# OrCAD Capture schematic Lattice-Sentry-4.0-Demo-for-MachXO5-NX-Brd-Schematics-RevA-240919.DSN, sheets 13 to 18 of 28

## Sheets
13 Certus Pro NX Bank 7 (BMC): size B
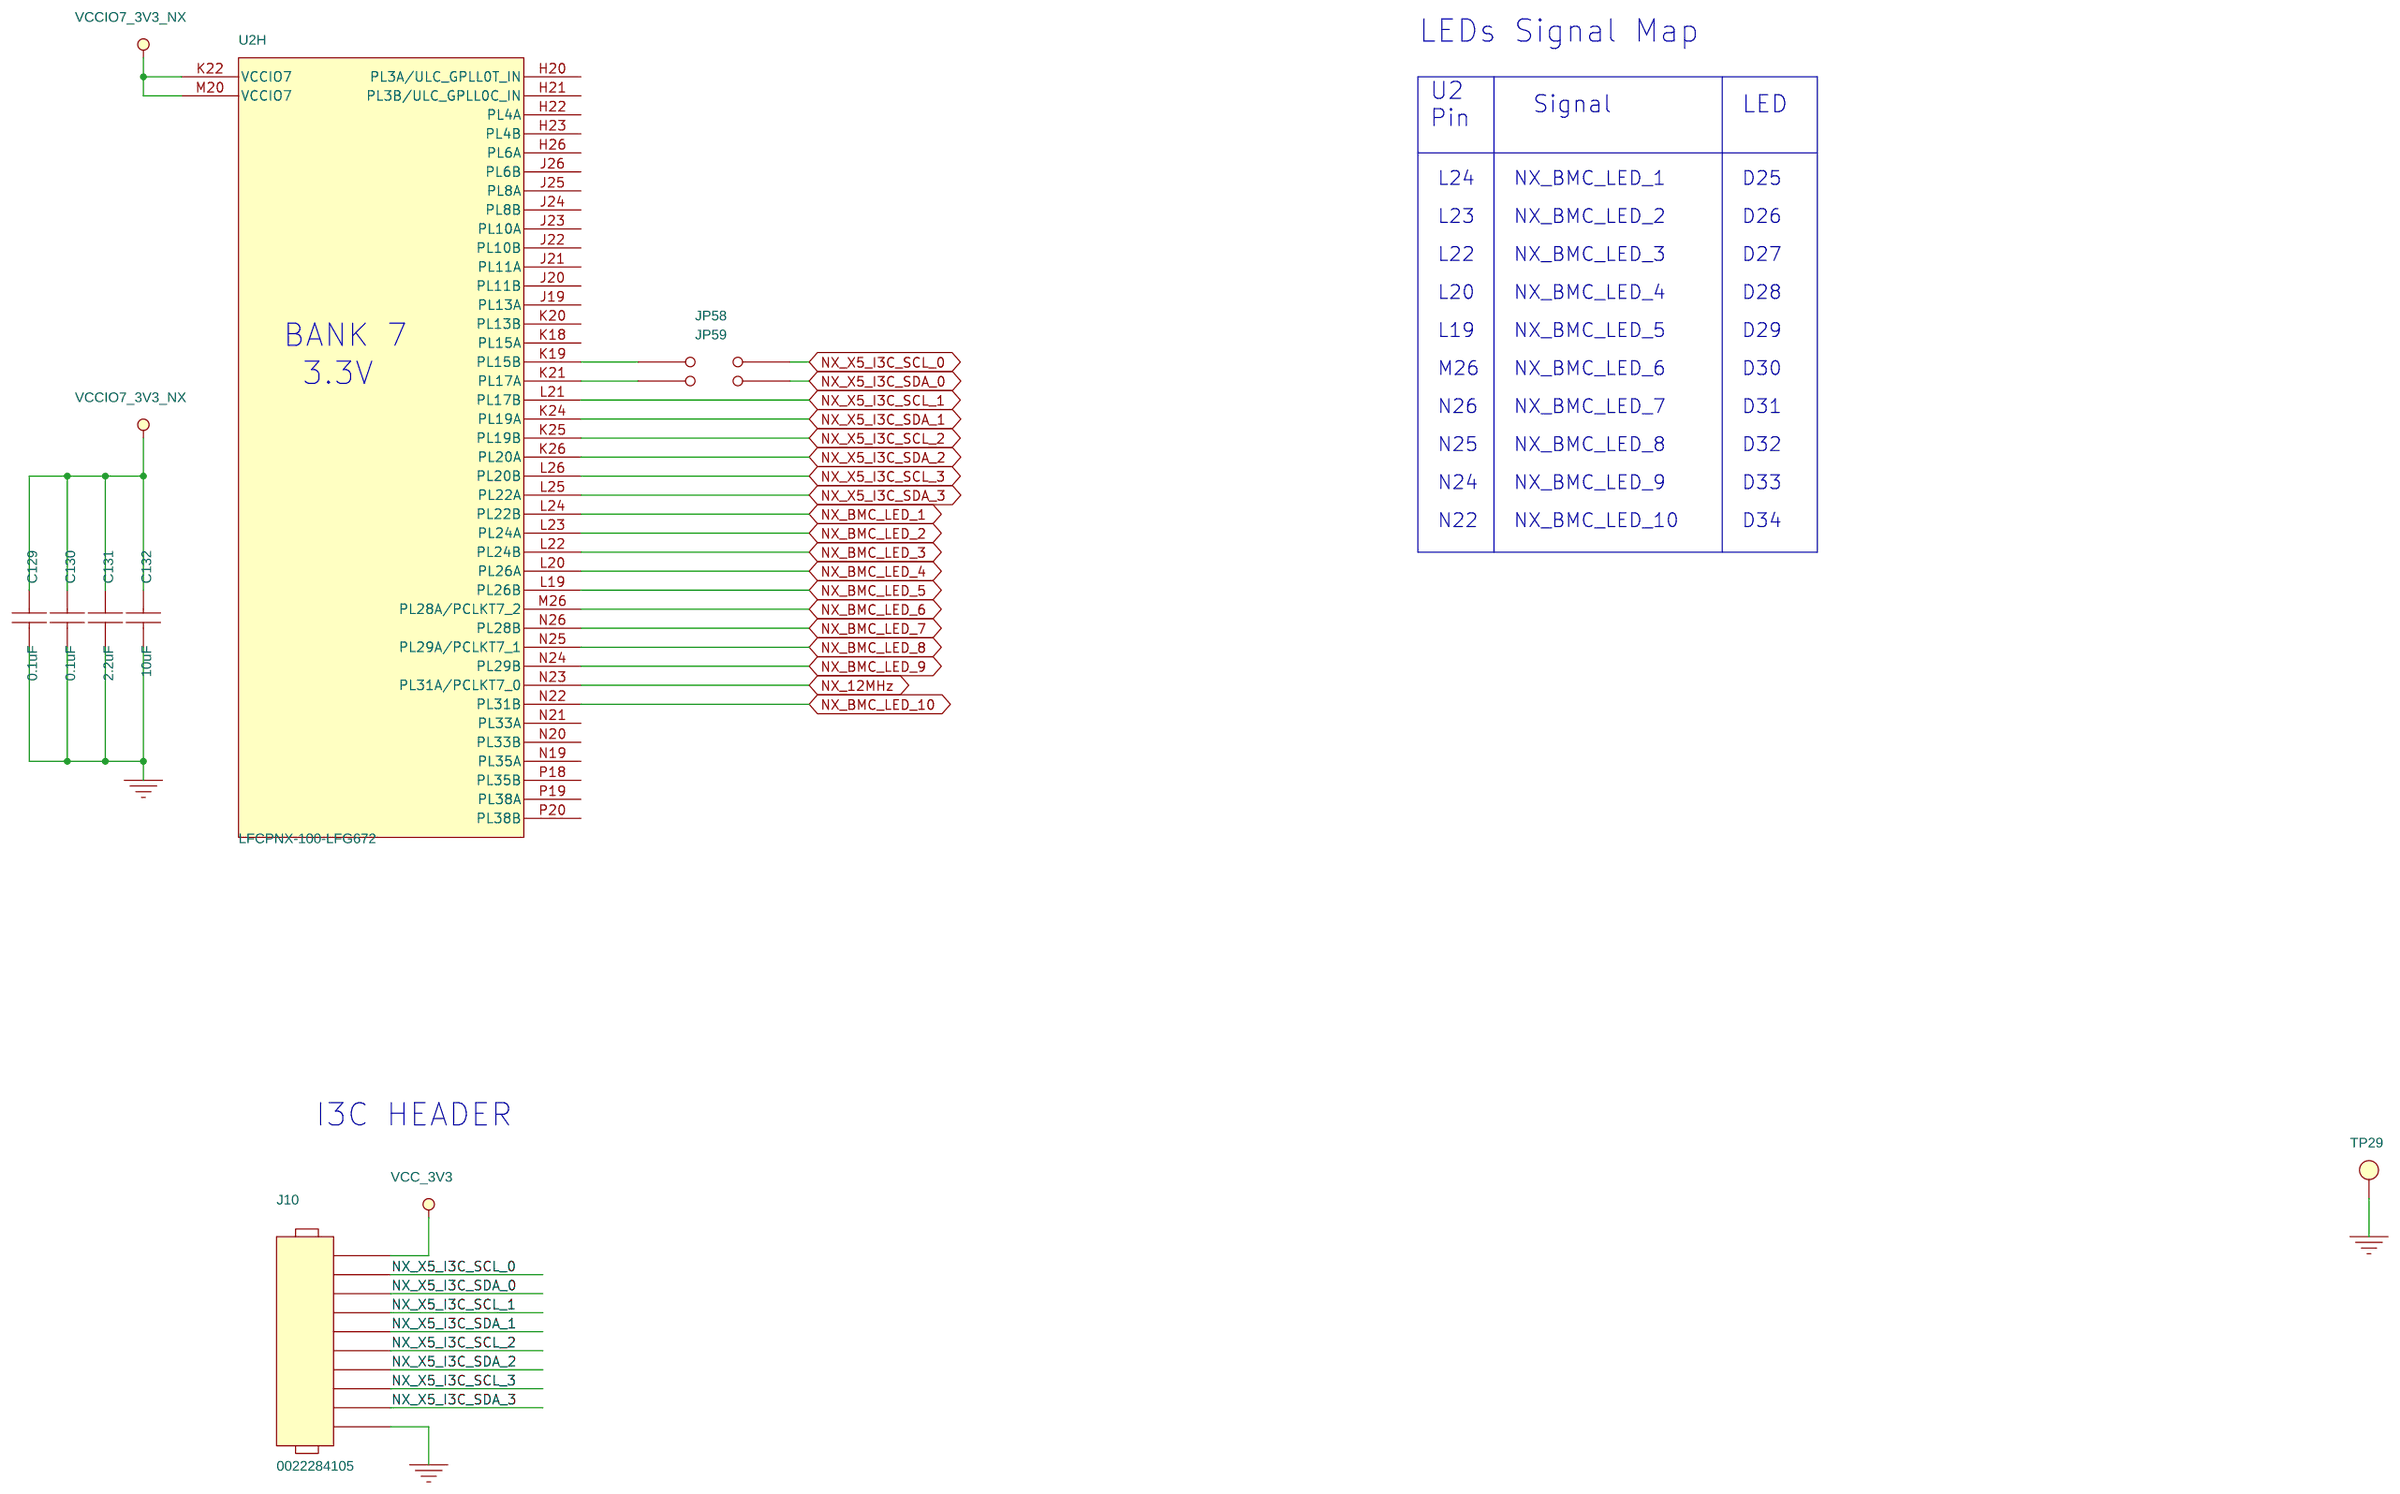
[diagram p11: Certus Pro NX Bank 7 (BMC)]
14 Certus Pro NX Bank2,6(PCH): size B
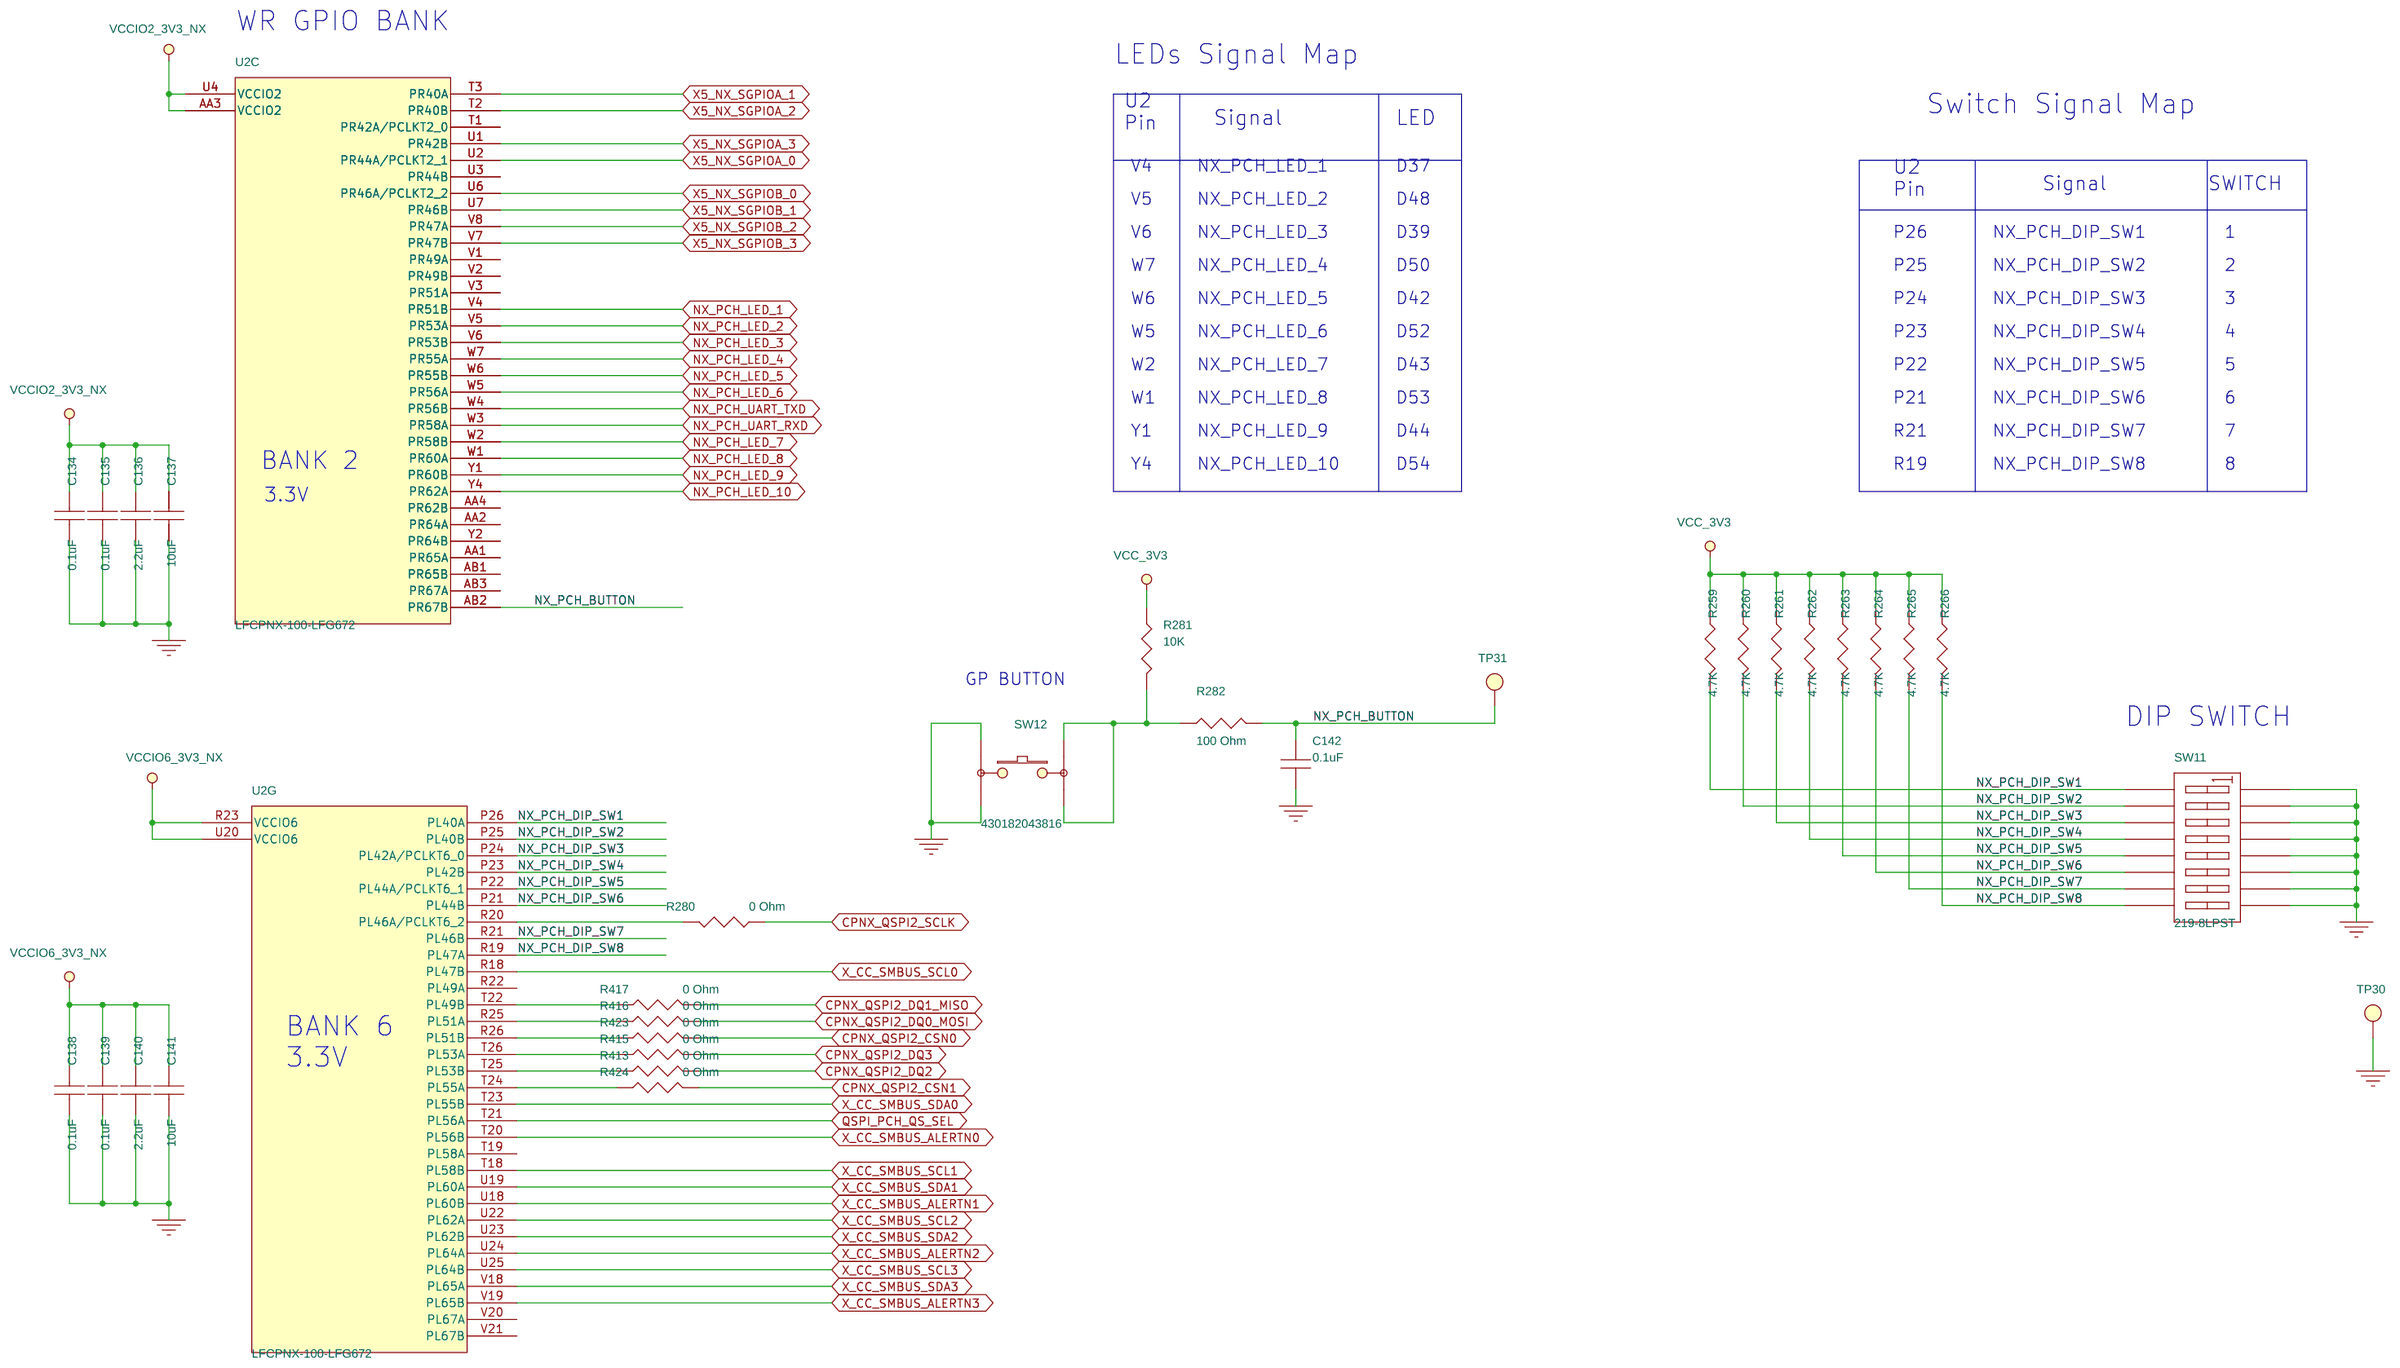
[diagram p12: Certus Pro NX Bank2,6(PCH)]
15 Certus Pro NX Bank3,4,A(PCH): size B
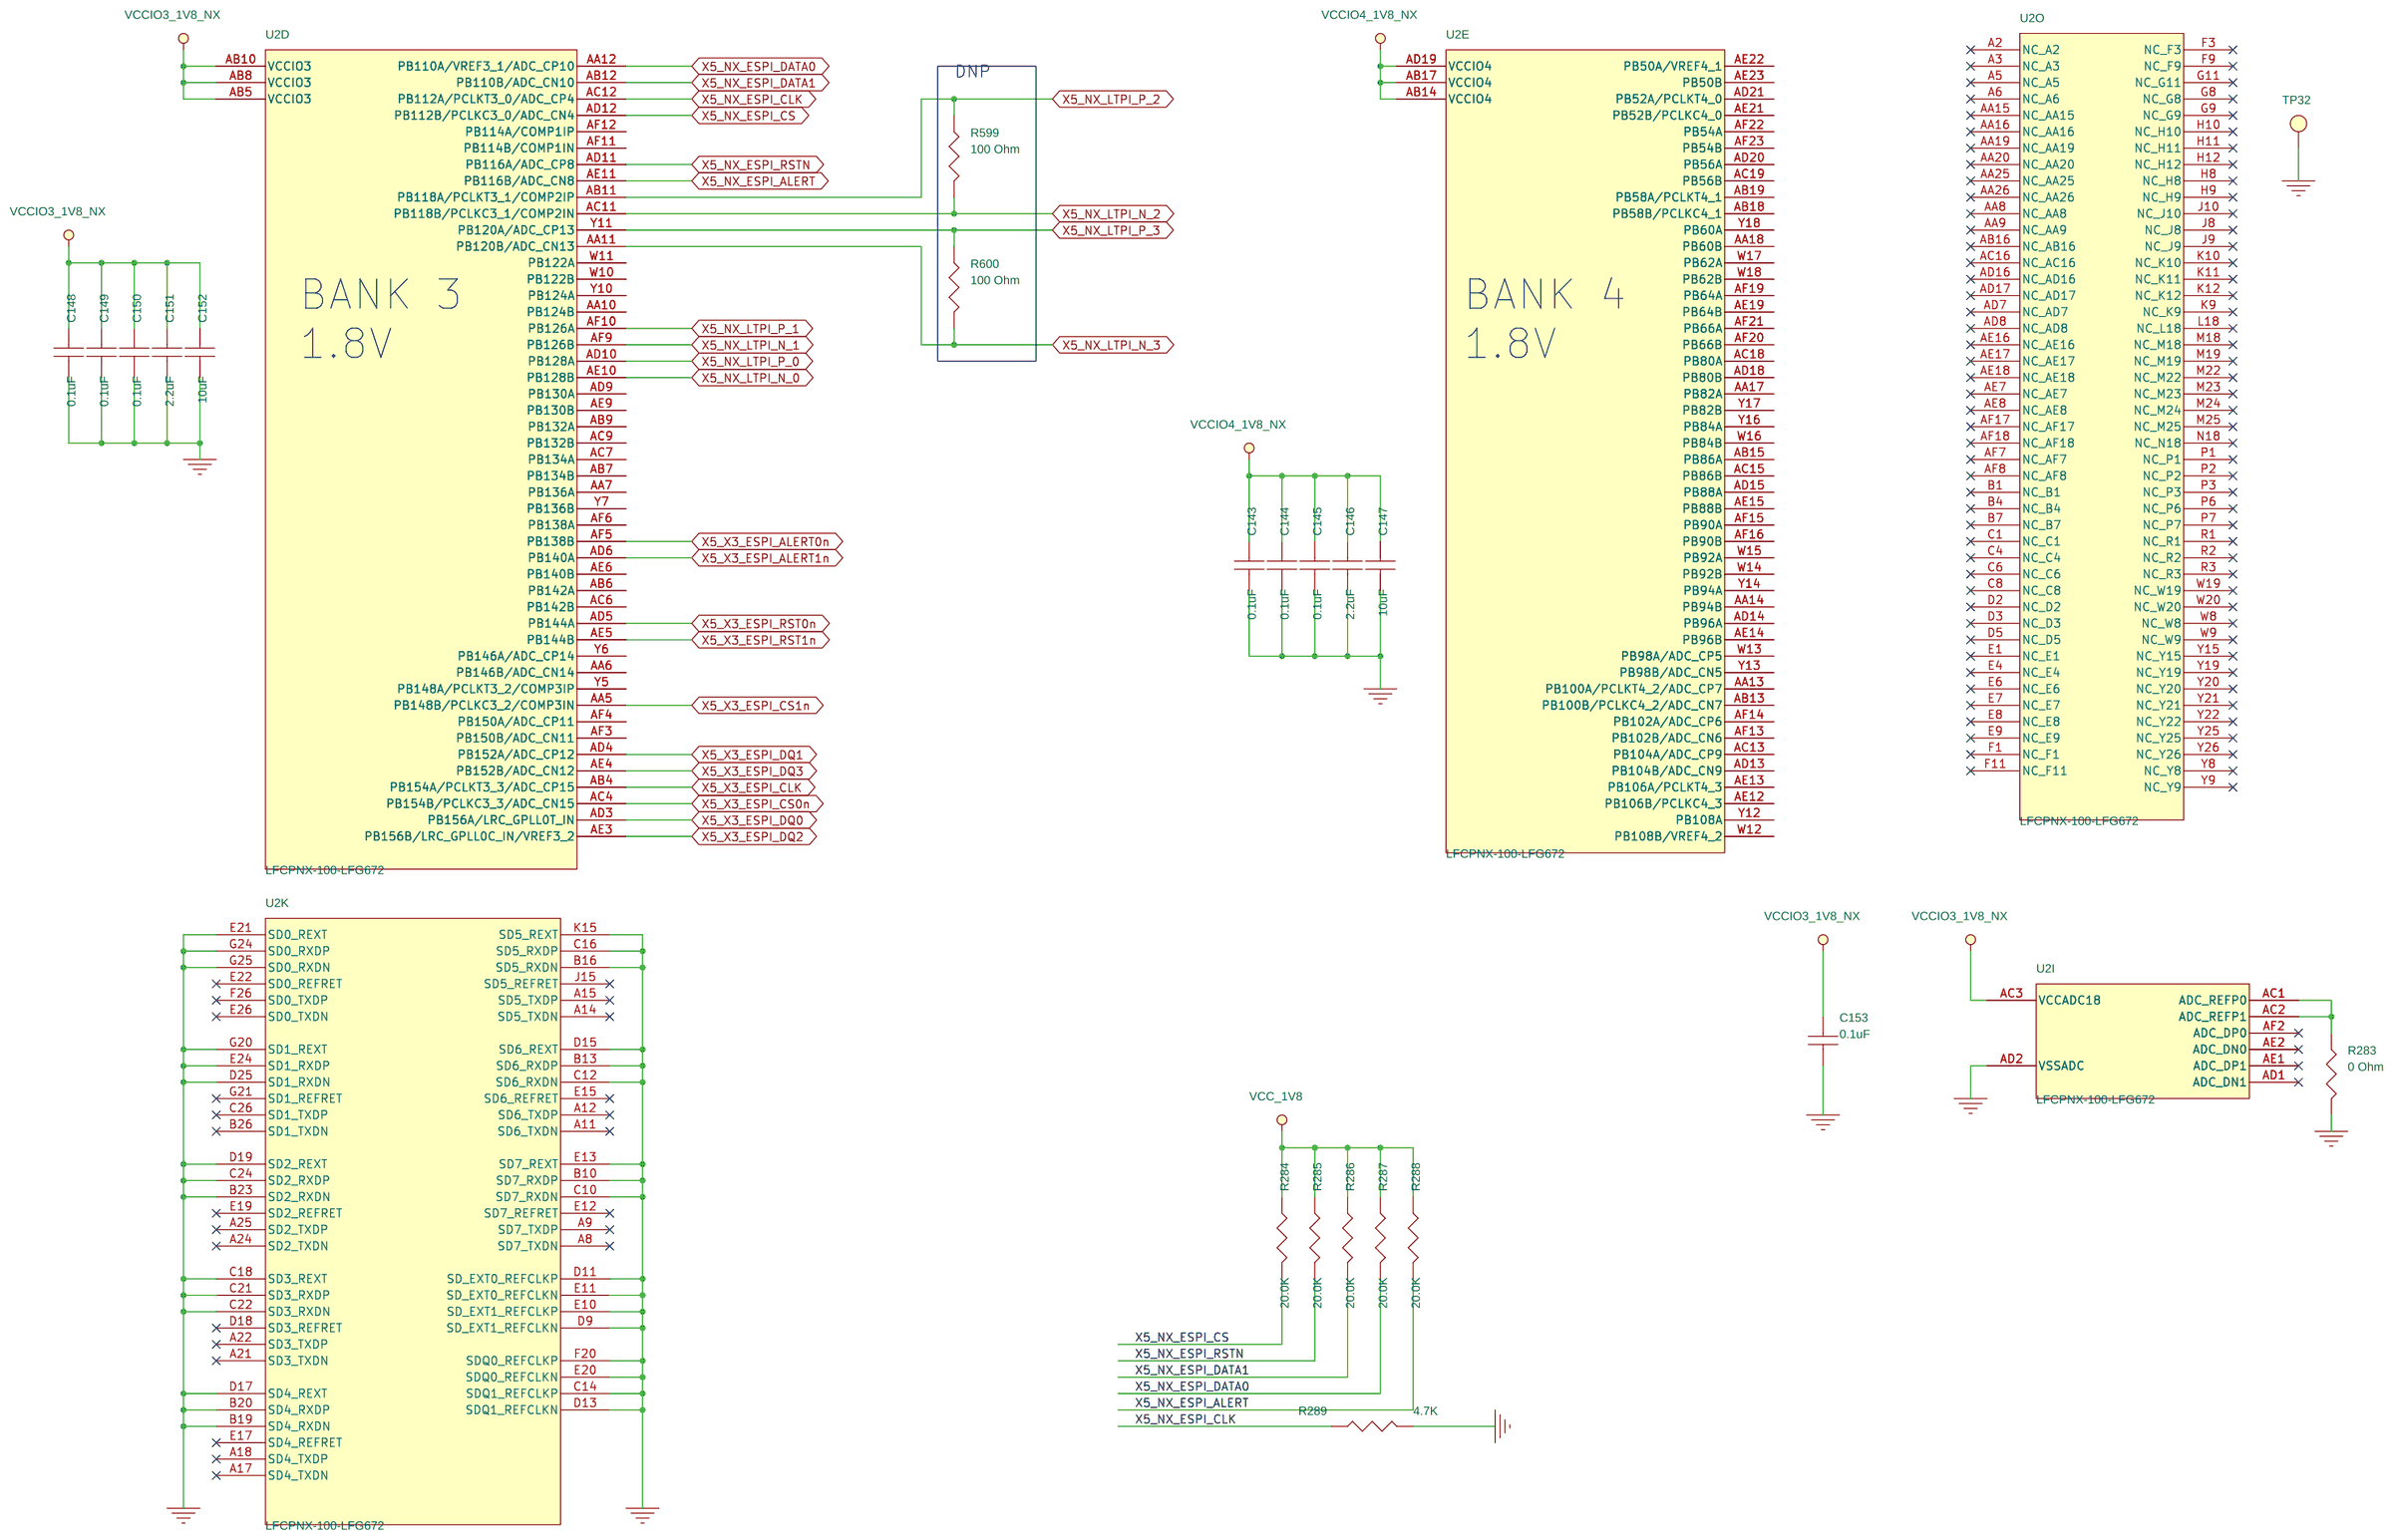
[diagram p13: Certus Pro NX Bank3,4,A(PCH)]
16 Certus Pro NX Power: size B
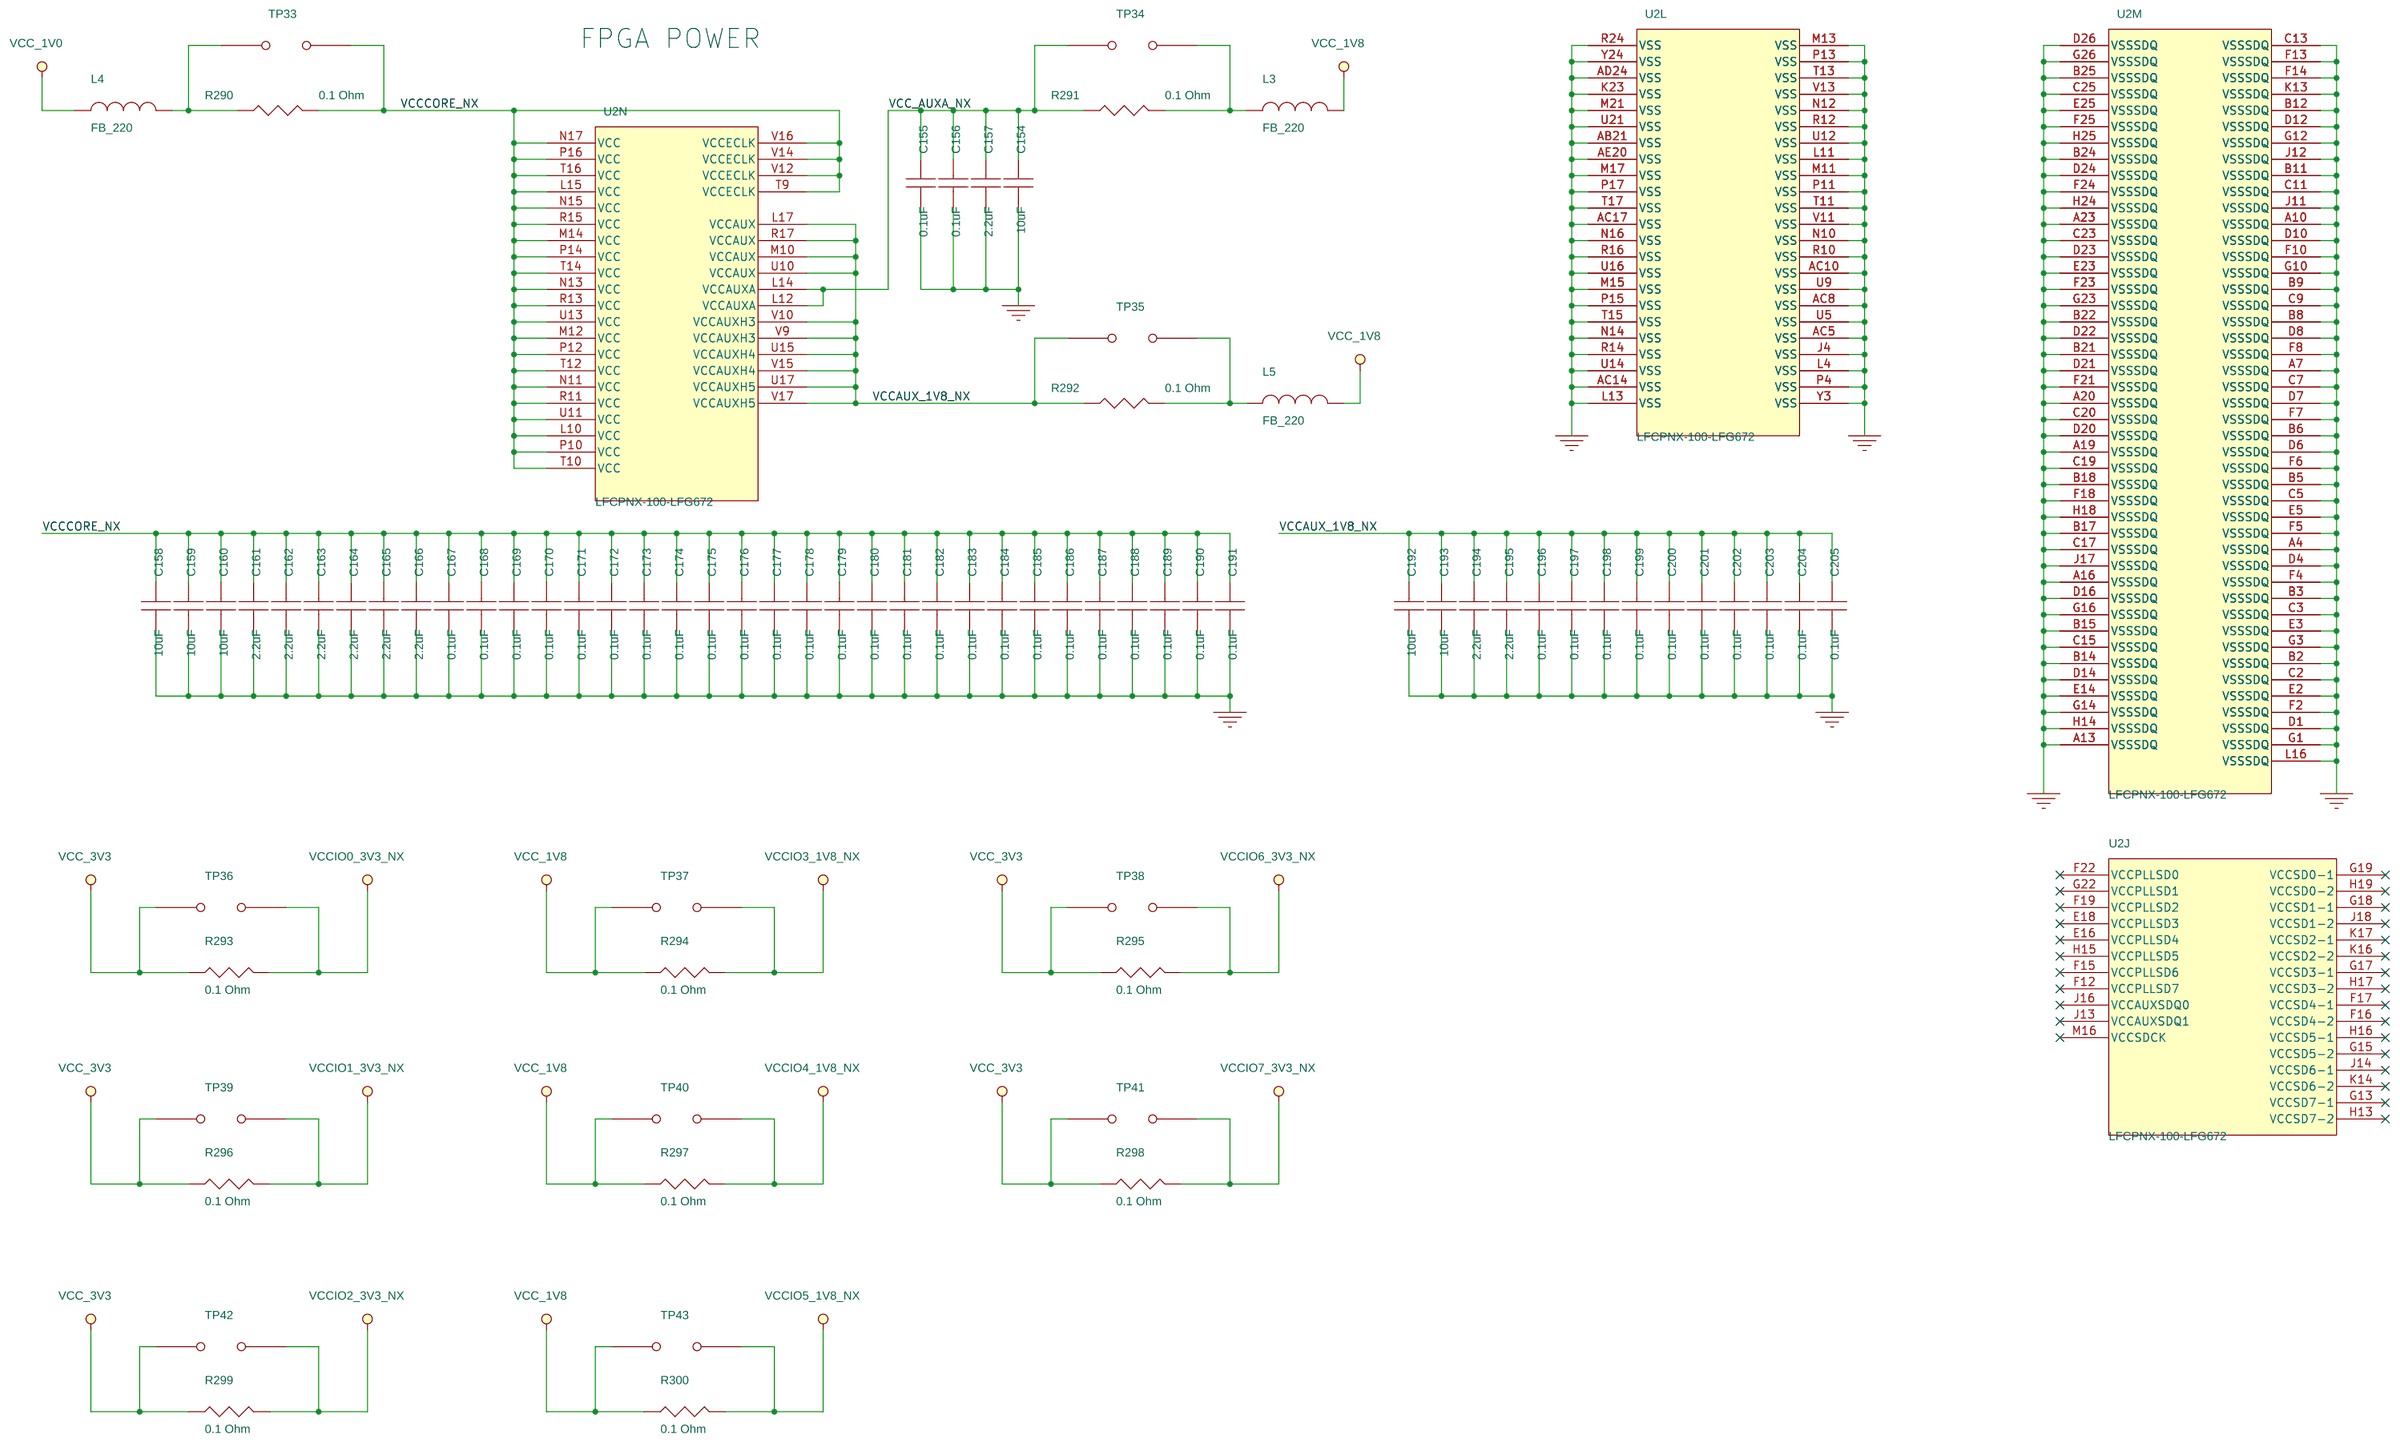
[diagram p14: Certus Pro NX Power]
17 LCMXO3D BANK0: size B
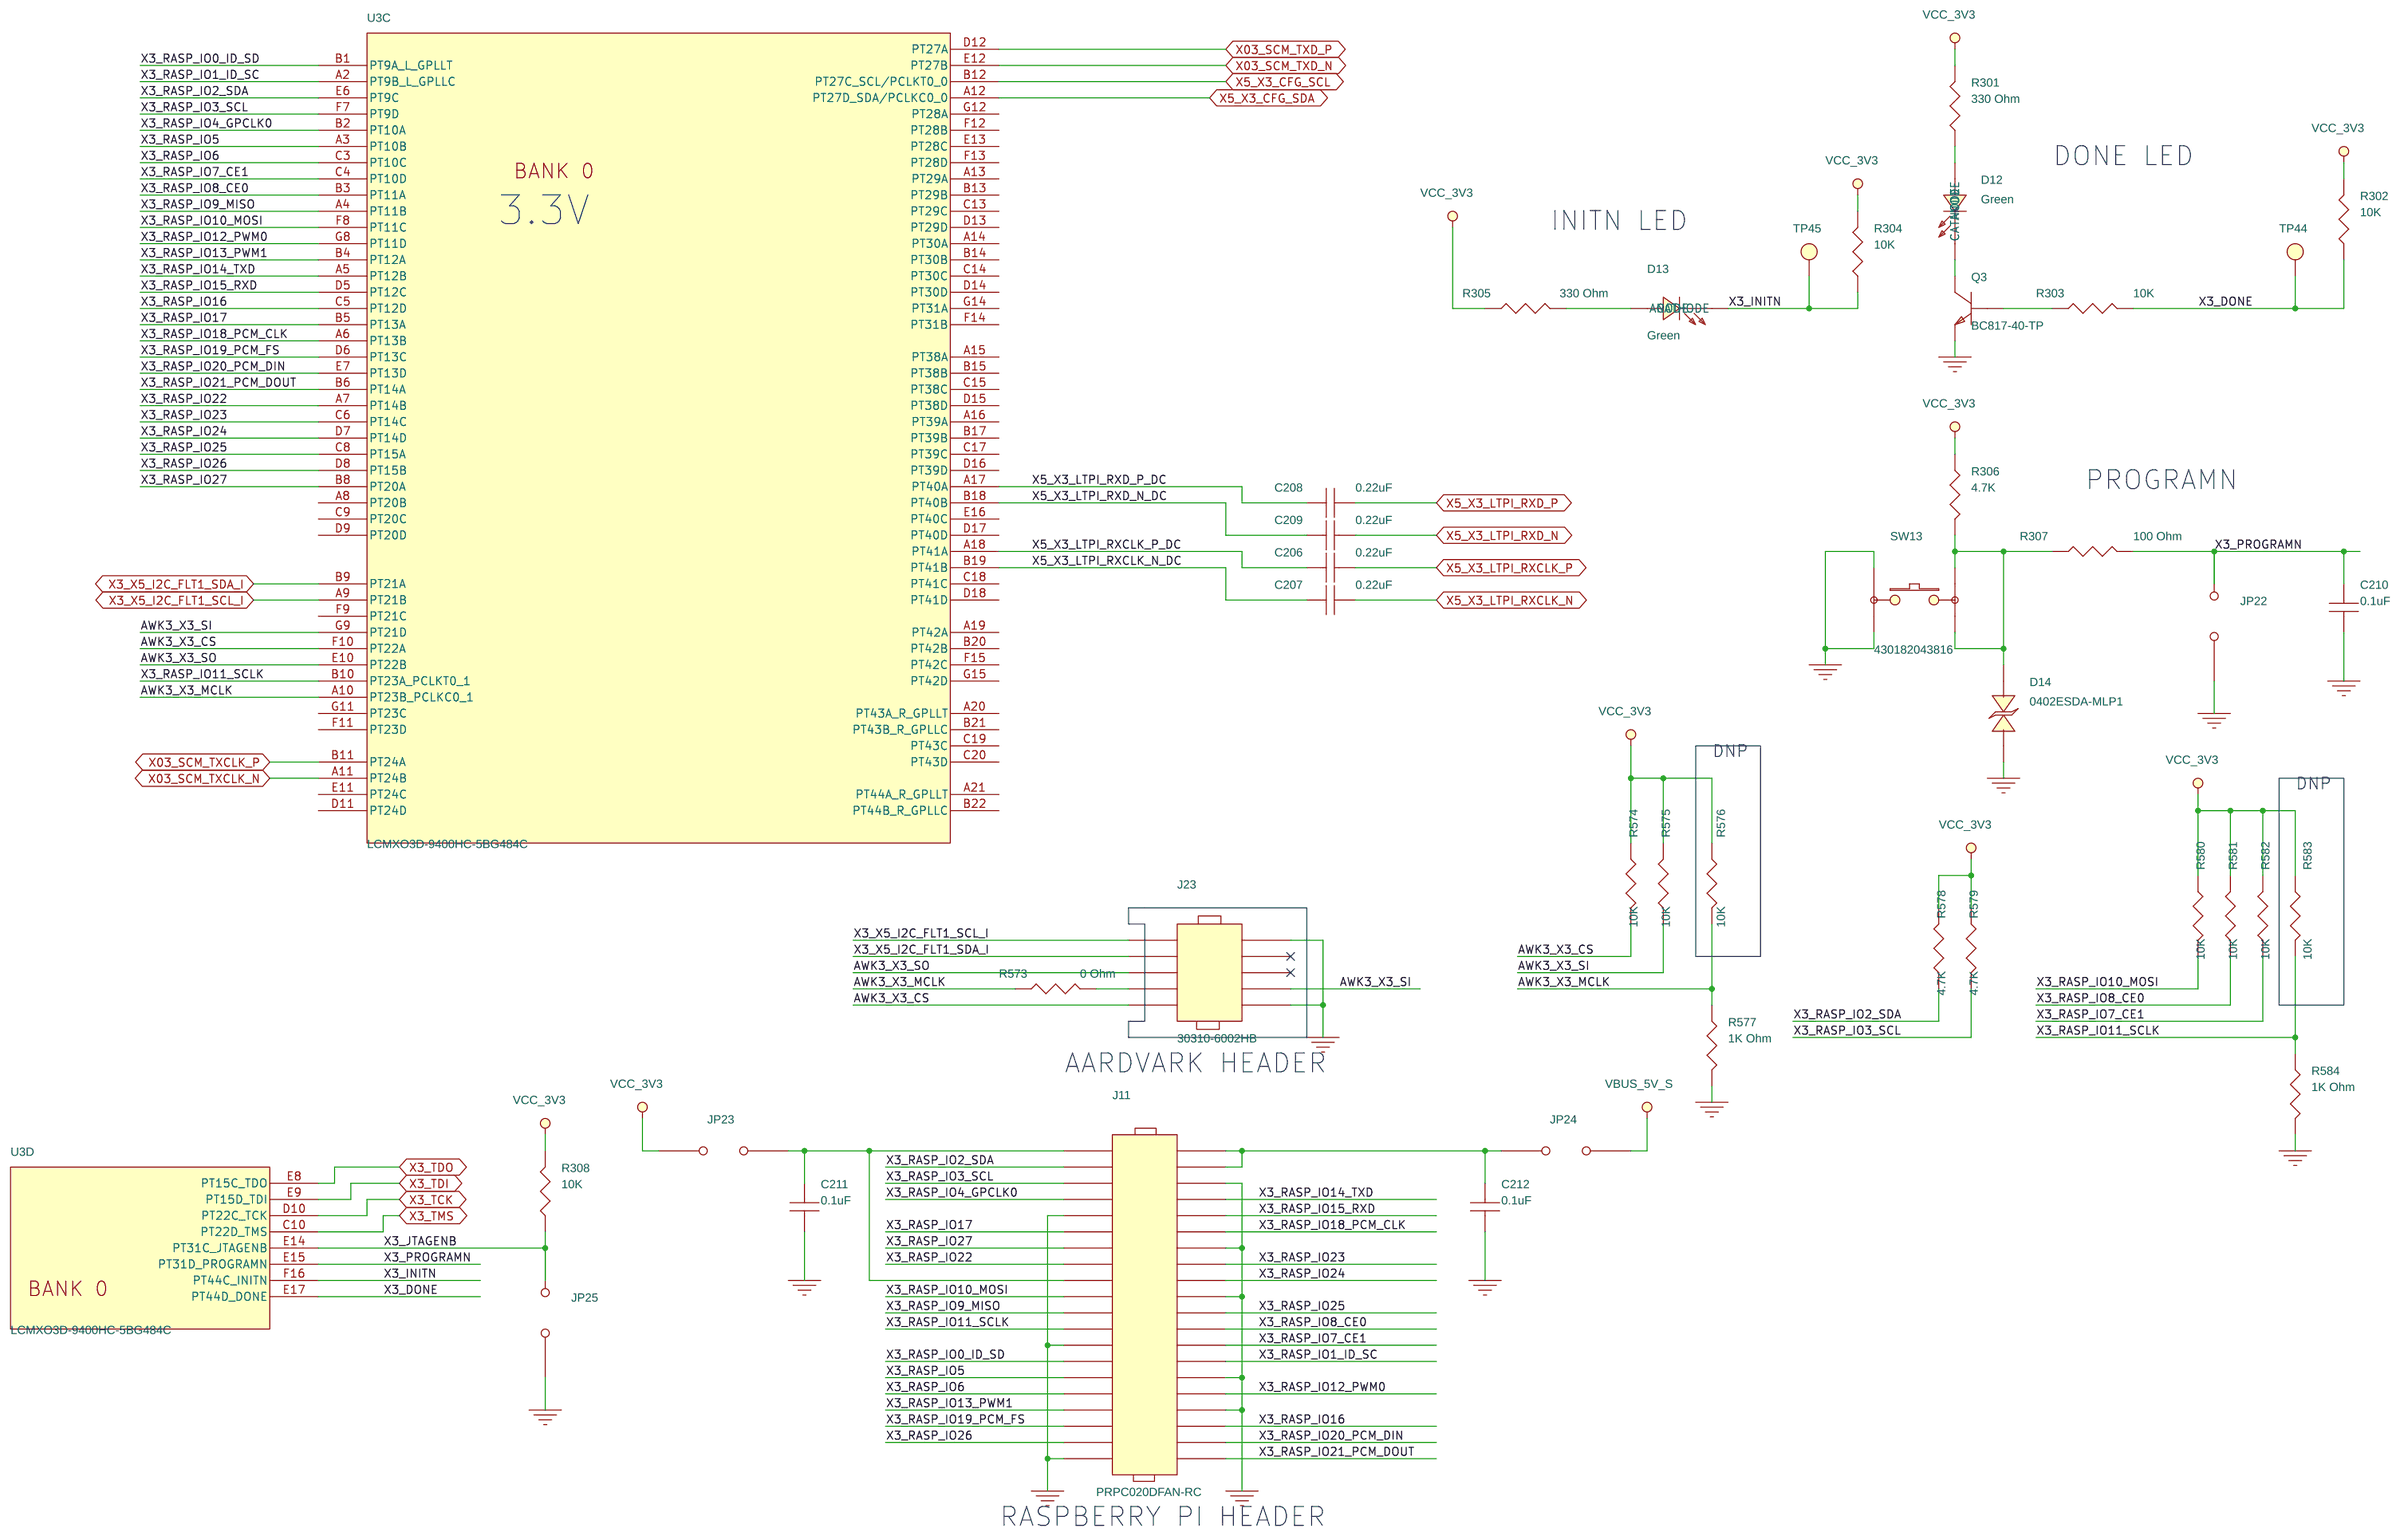
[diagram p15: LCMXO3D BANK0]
18 LCMXO3D BANK1: size B
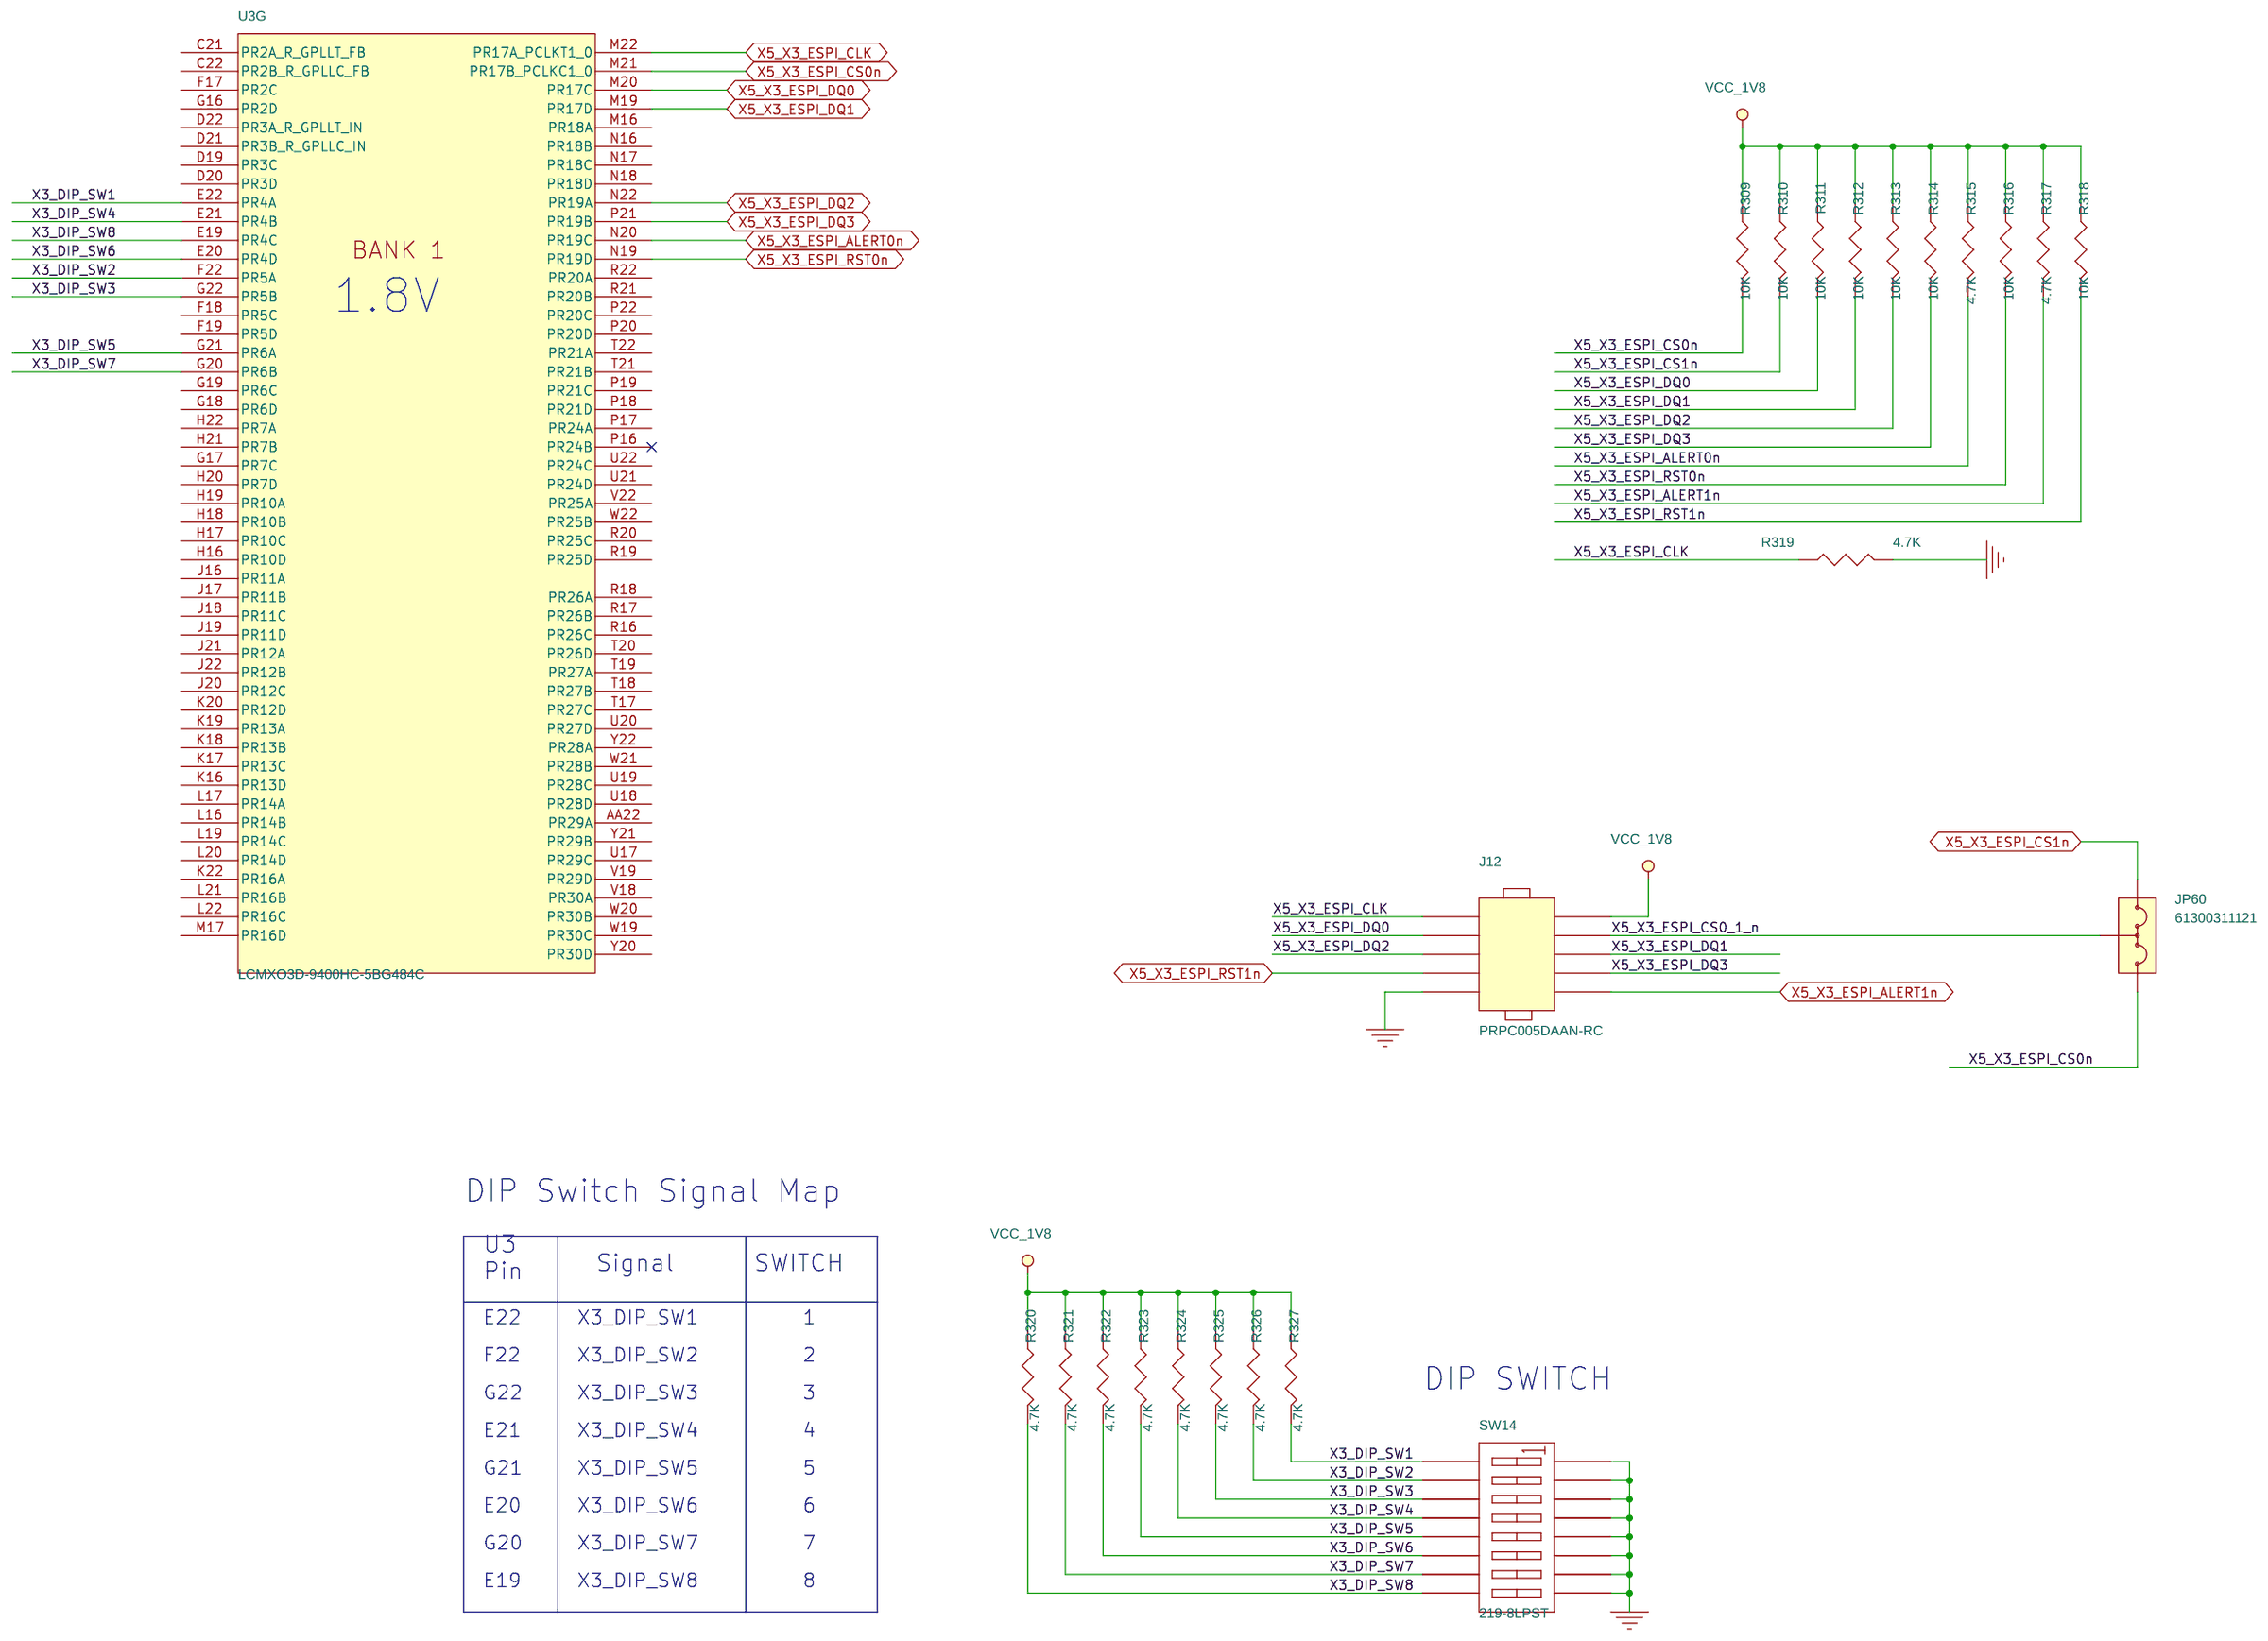
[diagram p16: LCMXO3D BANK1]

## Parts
sheet Certus Pro NX Bank2,6(PCH)
C134  0.1uF  [C0402-L]
C135  0.1uF  [C0402-L]
C136  2.2uF  [C0603-L]
C137  10uF  [C0805-L]
C138  0.1uF  [C0402-L]
C139  0.1uF  [C0402-L]
C140  2.2uF  [C0603-L]
C141  10uF  [C0805-L]
C142  0.1uF  [C0402-L]
R259  4.7K  [R0402-L]
R260  4.7K  [R0402-L]
R261  4.7K  [R0402-L]
R262  4.7K  [R0402-L]
R263  4.7K  [R0402-L]
R264  4.7K  [R0402-L]
R265  4.7K  [R0402-L]
R266  4.7K  [R0402-L]
R280  0 Ohm  [R0402-L]
R281  10K  [R0402-L]
R282  100 Ohm  [R0402-L]
R413  0 Ohm  [R0402-L]
R415  0 Ohm  [R0402-L]
R416  0 Ohm  [R0402-L]
R417  0 Ohm  [R0402-L]
R423  0 Ohm  [R0402-L]
R424  0 Ohm  [R0402-L]
SW11  219-8LPST  [219-8LPST_CTS]
SW12  430182043816  [SOIC_82043816_WRE]
TP30  TP1  [TPd39c60]
TP31  TP1  [TPd39c60]
sheet Certus Pro NX Bank3,4,A(PCH)
C143  0.1uF  [C0402-L]
C144  0.1uF  [C0402-L]
C145  0.1uF  [C0402-L]
C146  2.2uF  [C0603-L]
C147  10uF  [C0805-L]
C148  0.1uF  [C0402-L]
C149  0.1uF  [C0402-L]
C150  0.1uF  [C0402-L]
C151  2.2uF  [C0603-L]
C152  10uF  [C0805-L]
C153  0.1uF  [C0402-L]
R283  0 Ohm  [R0402-L]
R284  20.0K  [R0402-L]
R285  20.0K  [R0402-L]
R286  20.0K  [R0402-L]
R287  20.0K  [R0402-L]
R288  20.0K  [R0402-L]
R289  4.7K  [R0402-L]
R599  100 Ohm  [R0402-L]
R600  100 Ohm  [R0402-L]
TP32  TP1  [TPd39c60]
sheet Certus Pro NX Bank 7 (BMC)
C129  0.1uF  [C0402-L]
C130  0.1uF  [C0402-L]
C131  2.2uF  [C0603-L]
C132  10uF  [C0805-L]
J10  0022284105  [22-28-4105_MOL]
JP58  Jumper  [CONN2_M20-999_1x2_HRW]
JP59  Jumper  [CONN2_M20-999_1x2_HRW]
TP29  TP1  [TPd39c60]
sheet Certus Pro NX Power
C154  10uF  [C0805-L]
C155  0.1uF  [C0402-L]
C156  0.1uF  [C0402-L]
C157  2.2uF  [C0603-L]
C158  10uF  [C0805-L]
C159  10uF  [C0805-L]
C160  10uF  [C0805-L]
C161  2.2uF  [C0603-L]
C162  2.2uF  [C0603-L]
C163  2.2uF  [C0603-L]
C164  2.2uF  [C0603-L]
C165  2.2uF  [C0603-L]
C166  2.2uF  [C0603-L]
C167  0.1uF  [C0402-L]
C168  0.1uF  [C0402-L]
C169  0.1uF  [C0402-L]
C170  0.1uF  [C0402-L]
C171  0.1uF  [C0402-L]
C172  0.1uF  [C0402-L]
C173  0.1uF  [C0402-L]
C174  0.1uF  [C0402-L]
C175  0.1uF  [C0402-L]
C176  0.1uF  [C0402-L]
C177  0.1uF  [C0402-L]
C178  0.1uF  [C0402-L]
C179  0.1uF  [C0402-L]
C180  0.1uF  [C0402-L]
C181  0.1uF  [C0402-L]
C182  0.1uF  [C0402-L]
C183  0.1uF  [C0402-L]
C184  0.1uF  [C0402-L]
C185  0.1uF  [C0402-L]
C186  0.1uF  [C0402-L]
C187  0.1uF  [C0402-L]
C188  0.1uF  [C0402-L]
C189  0.1uF  [C0402-L]
C190  0.1uF  [C0402-L]
C191  0.1uF  [C0402-L]
C192  10uF  [C0805-L]
C193  10uF  [C0805-L]
C194  2.2uF  [C0603-L]
C195  2.2uF  [C0603-L]
C196  0.1uF  [C0402-L]
C197  0.1uF  [C0402-L]
C198  0.1uF  [C0402-L]
C199  0.1uF  [C0402-L]
C200  0.1uF  [C0402-L]
C201  0.1uF  [C0402-L]
C202  0.1uF  [C0402-L]
C203  0.1uF  [C0402-L]
C204  0.1uF  [C0402-L]
C205  0.1uF  [C0402-L]
L3  FB_220  [IND_1608_TDK]
L4  FB_220  [IND_1608_TDK]
L5  FB_220  [IND_1608_TDK]
R290  0.1 Ohm  [R0603-L]
R291  0.1 Ohm  [R0603-L]
R292  0.1 Ohm  [R0603-L]
R293  0.1 Ohm  [R0603-L]
R294  0.1 Ohm  [R0603-L]
R295  0.1 Ohm  [R0603-L]
R296  0.1 Ohm  [R0603-L]
R297  0.1 Ohm  [R0603-L]
R298  0.1 Ohm  [R0603-L]
R299  0.1 Ohm  [R0603-L]
R300  0.1 Ohm  [R0603-L]
TP33  Jumper  [CONN2_M20-999_1x2_HRW]
TP34  Jumper  [CONN2_M20-999_1x2_HRW]
TP35  Jumper  [CONN2_M20-999_1x2_HRW]
TP36  Jumper  [CONN2_M20-999_1x2_HRW]
TP37  Jumper  [CONN2_M20-999_1x2_HRW]
TP38  Jumper  [CONN2_M20-999_1x2_HRW]
TP39  Jumper  [CONN2_M20-999_1x2_HRW]
TP40  Jumper  [CONN2_M20-999_1x2_HRW]
TP41  Jumper  [CONN2_M20-999_1x2_HRW]
TP42  Jumper  [CONN2_M20-999_1x2_HRW]
TP43  Jumper  [CONN2_M20-999_1x2_HRW]
U2  LFCPNX-100-LFG672  [fcBGA-100p27x27-672]  (sections A,B,C,D,E,F,G,H,I,J,K,L,M,N,O)
sheet LCMXO3D BANK0
C206  0.22uF  [C0402-L]
C207  0.22uF  [C0402-L]
C208  0.22uF  [C0402-L]
C209  0.22uF  [C0402-L]
C210  0.1uF  [C0402-L]
C211  0.1uF  [C0402-L]
C212  0.1uF  [C0402-L]
D12  Green  [LED0603]
D13  Green  [LED0603]
D14  0402ESDA-MLP1  [TVS0402]
J11  PRPC020DFAN-RC  [AMPHENOL_10129381-940002BLF]
J23  30310-6002HB  [CONN_30310-6002HB_3MM]
JP22  Jumper  [CONN2_M20-999_1x2_HRW]
JP23  Jumper  [CONN2_M20-999_1x2_HRW]
JP24  Jumper  [CONN2_M20-999_1x2_HRW]
JP25  Jumper  [CONN2_M20-999_1x2_HRW]
Q3  BC817-40-TP  [SOT-23-3]
R301  330 Ohm  [R0402-L]
R302  10K  [R0402-L]
R303  10K  [R0402-L]
R304  10K  [R0402-L]
R305  330 Ohm  [R0402-L]
R306  4.7K  [R0402-L]
R307  100 Ohm  [R0402-L]
R308  10K  [R0402-L]
R573  0 Ohm  [R0402-L]
R574  10K  [R0402-L]
R575  10K  [R0402-L]
R576  10K  [R0402-L]
R577  1K Ohm  [R0402-L]
R578  4.7K  [R0402-L]
R579  4.7K  [R0402-L]
R580  10K  [R0402-L]
R581  10K  [R0402-L]
R582  10K  [R0402-L]
R583  10K  [R0402-L]
R584  1K Ohm  [R0402-L]
SW13  430182043816  [SOIC_82043816_WRE]
TP44  TP1  [TPd39c60]
TP45  TP1  [TPd39c60]
sheet LCMXO3D BANK1
J12  PRPC005DAAN-RC  [CON10_2X5_TU_TSW_SAI]
JP60  61300311121  [CONN03_6130_7P62X2P54_WRE]
R309  10K  [R0402-L]
R310  10K  [R0402-L]
R311  10K  [R0402-L]
R312  10K  [R0402-L]
R313  10K  [R0402-L]
R314  10K  [R0402-L]
R315  4.7K  [R0402-L]
R316  10K  [R0402-L]
R317  4.7K  [R0402-L]
R318  10K  [R0402-L]
R319  4.7K  [R0402-L]
R320  4.7K  [R0402-L]
R321  4.7K  [R0402-L]
R322  4.7K  [R0402-L]
R323  4.7K  [R0402-L]
R324  4.7K  [R0402-L]
R325  4.7K  [R0402-L]
R326  4.7K  [R0402-L]
R327  4.7K  [R0402-L]
SW14  219-8LPST  [219-8LPST_CTS]
sheet LCMXO3D BANK2_3_4_5
U3  LCMXO3D-9400HC-5BG484C  [caBGA-080p19x19-484]  (sections A,B,C,D,E,F,G)

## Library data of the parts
C129 C130 C134 C135 C138 C139 C142-C145 C148-C150 C153 C155 C156 C167-C191 C196-C205 C210-C212 = CAP_NP: 0.1 µF ±10% 50V Ceramic Capacitor X7R 0402 (1005 Metric); Manufacturer: Murata; Manufacturer Part Number: GRM155R71H104KE14J; Part Number: GRM155R71H104KE14J; Part type: Ceramic; Tolerance: 10%; Voltage: 50V; Datasheet: https://search.murata.co.jp/Ceramy/image/img/A01X/G101/ENG/GRM155R71H104KE14-01.pdf
C131 C136 C140 C146 C151 C157 C161-C166 C194 C195 = CAP_NP: 2.2 µF ±10% 25V Ceramic Capacitor X5R 0603 (1608 Metric); Manufacturer: Murata; Manufacturer Part Number: GRM188R61E225KA12J; Part Number: GRM188R61E225KA12J; Part type: Ceramic; Tolerance: 10%; Voltage: 25V; Datasheet: https://search.murata.co.jp/Ceramy/image/img/A01X/G101/ENG/GRM188R61E225KA12-01.pdf
C132 C137 C141 C147 C152 C154 C158-C160 C192 C193 = CAP_NP: 10 µF ±10% 25V Ceramic Capacitor X5R 0805 (2012 Metric); Manufacturer: Murata; Manufacturer Part Number: GRM21BR61E106KA73K; Part Number: GRM21BR61E106KA73K; Part type: Ceramic; Tolerance: 10%; Voltage: 25V; Datasheet: https://search.murata.co.jp/Ceramy/image/img/A01X/G101/ENG/GRM21BR61E106KA73-01.pdf
R259-R266 R289 R306 R315 R317 R319-R327 R578 R579 = R: 4.7 kOhms ±1% 0.063W, 1/16W Chip Resistor 0402 (1005 Metric) Thick Film; Manufacturer: Yageo; Manufacturer Part Number: RC0402FR-074K7P; Part Number: RC0402FR-074K7P; Part type: Thick Film; Power: 1/16W; Tolerance: 1%; Datasheet: https://www.yageo.com/upload/media/product/products/datasheet/rchip/PYu-RC_51_RoHS_P_4.pdf
R280 = R: 0 Ohms Jumper Chip Resistor 0402 (1005 Metric) Moisture Resistant Thick Film; MANUFACTURER: Yageo; MFR PART NO.: RC0603JR-070RL; Manufacturer Part Number: RC0402FR-070RL; PACKAGE: 0603; PART DESCRIPTION: RES 0 OHM JUMPER 1/10W 0603; Part Number: RC0402FR-070RL; Part type: Thick Film; Datasheet: https://www.yageo.com/upload/media/product/productsearch/datasheet/rchip/PYu-RC_Group_51_RoHS_L_12.pdf
R281 R302-R304 R308-R314 R316 R318 R574 R575 R580-R582 = R: 10 kOhms ±1% 0.063W, 1/16W Chip Resistor 0402 (1005 Metric) Thick Film; Manufacturer: Yageo; Manufacturer Part Number: RC0402FR-0710KP; Part Number: RC0402FR-0710KP; Part type: Thick Film; Power: 1/16W; Tolerance: 1%; Datasheet: https://www.yageo.com/upload/media/product/products/datasheet/rchip/PYu-RC_51_RoHS_P_4.pdf
R282 R307 = R: 100 Ohms ±1% 0.063W, 1/16W Chip Resistor 0402 (1005 Metric) Thick Film; Manufacturer: Yageo; Manufacturer Part Number: RC0402FR-07100KP; Part Number: RC0402FR-07100KP; Part type: Thick Film; Power: 1/16W; Tolerance: 1%; Datasheet: https://www.yageo.com/upload/media/product/productsearch/datasheet/rchip/PYu-RC_Group_51_RoHS_L_12.pdf
R283 R413 R415-R417 R423 R424 R573 = R: 0 Ohms Jumper Chip Resistor 0402 (1005 Metric) Moisture Resistant Thick Film; Manufacturer: Yageo; Manufacturer Part Number: RC0402FR-070RL; Part Number: RC0402FR-070RL; Part type: Thick Film; Datasheet: https://www.yageo.com/upload/media/product/productsearch/datasheet/rchip/PYu-RC_Group_51_RoHS_L_12.pdf
SW11 SW14 = SW_DIP-8: Dip Switch SPST 8 Position Surface Mount Slide (Standard) Actuator 100mA 20VDC / Dip Switch SPST 5 Position Surface Mount Slide (Standard) Actuator 100mA 20VDC; MFR PART NO.: TDA08H0SB1; Manufacturer: CST; PACKAGE: SMD; PART DESCRIPTION: SWITCH SLIDE DIP SPST 25MA 24V; Datasheet: https://www.ctscorp.com/wp-content/uploads/219.pdf
SW12 SW13 = SW_PB-SPST-2: Tactile Switch SPST-NO Top Actuated Surface Mount; Manufacturer: Wurth; Datasheet: https://www.we-online.com/katalog/datasheet/4301x2xxx8x6.pdf
TP29-TP32 TP44 TP45 = TP1: Test Point 0.39"; Manufacturer: NA; Part Type: Test Point; Datasheet: NA
R284-R288 = R: 20 kOhms ±1% 0.063W, 1/16W Chip Resistor 0402 (1005 Metric) Moisture Resistant Thick Film; Manufacturer: Yageo; Manufacturer Part Number: RC0402FR-0720KL; Part Number: RC0402FR-0720KL; Part type: Thick Film; Power: 1/16W; Tolerance: 1%; Datasheet: https://www.yageo.com/upload/media/product/app/datasheet/rchip/pyu-rc_group_51_rohs_l.pdf
R599 R600 = R: 100 Ohms ±1% 0.063W, 1/16W Chip Resistor 0402 (1005 Metric) Thick Film; Assy: DNL; Manufacturer: Yageo; Manufacturer Part Number: RC0402FR-07100KP; Part Number: RC0402FR-07100KP; Part type: Thick Film; Power: 1/16W; Tolerance: 1%; Datasheet: https://www.yageo.com/upload/media/product/productsearch/datasheet/rchip/PYu-RC_Group_51_RoHS_L_12.pdf
J10 = HEADER_10: Connector Header Through Hole 10 position 0.100" (2.54mm); MFR PART NO.: 0022284101; Manufacturer: Molex; PACKAGE: TH; PART DESCRIPTION: CONN HEADER VERT 10POS 2.54MM; Part Type: Connector; Datasheet: https://www.molex.com/pdm_docs/sd/022284105_sd.pdf
JP58 JP59 TP33-TP43 = JUMPER: Connector Header Through Hole 2 position 0.100" (2.54mm); MANUFACTURER: Sullins; MFR PART NO.: 61300211121; Manufacturer Part Number: PREC002SAAN-RC; PACKAGE: TH; PART DESCRIPTION: CONN HEADER VERT 2POS 2.54MM; Part Number: PREC002SAAN-RC; Datasheet: https://media.digikey.com/PDF/Data%20Sheets/Sullins%20PDFs/z%20RzCzzzSzzN-RC,%20ST,11635-B.pdf
L3-L5 = INDUCTOR: 220 Ohms @ 100 MHz 1 Power Line Ferrite Bead 0603 (1608 Metric) 2.2A 50mOhm; Current: 2.2A; DCR: 50 mOhm; Manufacturer: Murata Electronics; Manufacturer Part Number: BLM18KG221SN1D; Part Number: BLM18KG221SN1D; Datasheet: https://www.murata.com/products/productdata/8796738650142/ENFA0003.pdf
R290-R300 = R: 100 mOhms ±1% 0.2W, 1/5W Chip Resistor 0603 (1608 Metric) Current Sense Metal Film; Manufacturer: Ohmite; Manufacturer Part Number: KDV06FR100ET; Part Number: KDV06FR100ET; Part type: Metal Film; Tolerance: 1%; Datasheet: https://www.ohmite.com/assets/docs/res_kdv.pdf?r=false
U2 = LFCPNX-100-LFG672: Lattice Lattice CertusPro-NX General Purpose FPGA on Nexus platform (28nm FD-SOI); MFR PART NO.: LFCPNX-100-9LFG672I; Manufacturer: Lattice Semiconductor; Manufacturer Part Number: LFCPNX-100-9LFG672C; PACKAGE: LFG672; PART DESCRIPTION: IC FPGA CERTUSPRO-NX; Part Number: LFCPNX-100-9LFG672C; Part Type: FPGA; Datasheet: https://www.latticesemi.com/view_document?document_id=53126
C206-C209 = CAP_NP: 0.22 µF ±10% 50V Ceramic Capacitor X5R 0402 (1005 Metric); Manufacturer: Murata; Manufacturer Part Number: GRM155R61H224KE01W; Part Number: GRM155R61H224KE01W; Part type: Ceramic; Tolerance: 10%; Voltage: 50V; Datasheet: https://search.murata.co.jp/Ceramy/image/img/A01X/G101/ENG/GRM155R61H224KE01-01A.pdf
D12 D13 = LED_0: Green 572nm LED indication - Discrete  2.2V 0603; Manufacturer: Rohm Semiconductor; Manufacturer Part Number: SML-D12M8WT86; Part Number: SML-D12M8WT86; Part type: LED; Voltage: 2.2V; Datasheet: https://fscdn.rohm.com/en/products/databook/datasheet/opto/led/chip_mono/sml-d12x8_d13x8-e.pdf
D14 = DIODE_TS_BI-DIR: SUPPRESSOR ESD 30VDC 0402 HFREE; Manufacturer: Eaton; Part type: ESD; Voltage: 30V; Datasheet: https://www.eaton.com/content/dam/eaton/products/electronic-components/resources/data-sheet/eaton-0402esda-mlp-esd-suppressor-data-sheet.pdf
J11 = HEADER_20X2: Connector Header Through Hole 40 position 0.100" (2.54mm); Manufacturer: Sullins; Part Type: Connector; Datasheet: https://drawings-pdf.s3.amazonaws.com/11636.pdf
J23 = HEADER_5x2: Connector Header Through Hole 10 position 0.100" (2.54mm); Manufacturer: 3M; Part Type: Connector; Datasheet: https://multimedia.3m.com/mws/media/22504O/3mtm-100-in-loprof-hdr-100x-100strt-ra-4-wall-ts0818.pdf
JP22-JP25 = JUMPER: Connector Header Through Hole 2 position 0.100" (2.54mm); Manufacturer: Sullins; Manufacturer Part Number: PREC002SAAN-RC; Part Number: PREC002SAAN-RC; Datasheet: https://media.digikey.com/PDF/Data%20Sheets/Sullins%20PDFs/z%20RzCzzzSzzN-RC,%20ST,11635-B.pdf
Q3 = NPN_BEC_0: Bipolar (BJT) Transistor NPN 45 V 800 mA 100MHz 310 mW Surface Mount SOT-23; Manufacturer: Micro Commercial; Part Type: BJT_NPN; Datasheet: https://www.mccsemi.com/pdf/Products/BC817-16~BC817-40(SOT-23).pdf
R301 R305 = R: 330 Ohms ±1% 0.063W, 1/16W Chip Resistor 0402 (1005 Metric) Moisture Resistant Thick Film; Manufacturer: Yageo; Manufacturer Part Number: RC0402FR-07330RL; Part Number: RC0402FR-07330RL; Part type: Thick Film; Power: 1/16W; Tolerance: 1%; Datasheet: https://www.yageo.com/upload/media/product/productsearch/datasheet/rchip/PYu-RC_Group_51_RoHS_L_12.pdf
R576 R583 = R: 10 kOhms ±1% 0.063W, 1/16W Chip Resistor 0402 (1005 Metric) Thick Film; Assy: DNL; Manufacturer: Yageo; Manufacturer Part Number: RC0402FR-0710KP; Part Number: RC0402FR-0710KP; Part type: Thick Film; Power: 1/16W; Tolerance: 1%; Datasheet: https://www.yageo.com/upload/media/product/products/datasheet/rchip/PYu-RC_51_RoHS_P_4.pdf
R577 R584 = R: 1 kOhms ±1% 0.063W, 1/16W Chip Resistor 0402 (1005 Metric) Thick Film; Manufacturer: Yageo; Manufacturer Part Number: RC0402FR-71K2P / RC0402FR-0733R2P; Part Number: RC0402FR-071KP / RC0402FR-0733R2P / RC0402FR-0733R2P; Part type: Thick Film; Power: 1/16W; Tolerance: 1%; Datasheet: https://www.yageo.com/upload/media/product/products/datasheet/rchip/PYu-RC_51_RoHS_P_4.pdf
J12 = HEADER_5X2: Connector Header Through Hole 10 position 0.100" (2.54mm); Manufacturer: Sullins; Part Type: Connector; Datasheet: https://drawings-pdf.s3.amazonaws.com/11636.pdf
JP60 = JUMP_3: Connector Header Through Hole 3 position 0.100" (2.54mm); Manufacturer: Wurth; Part Type: Connector; Datasheet: https://www.we-online.com/katalog/datasheet/6130xx11121.pdf
U3 = LCMXO3D-9400-BG484: FPGA - Field Programmable Gate Array Lattice MachXO3D; 9400LUTs 2.5V/3.3V; ID: 3; Manufacturer: Lattice Semiconductor; Part Type: FPGA; Datasheet: https://www.latticesemi.com/-/media/LatticeSemi/Documents/DataSheets/MachXO23/FPGA-DS-02026-0-90-MachXO3D-Device-Family.ashx?document_id=52590

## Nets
GND: C129.2 C130.2 C131.2 C132.2 C134.2 C135.2 C136.2 C137.2 C138.2 C139.2 C140.2 C141.2 C142.2 C143.2 C144.2 C145.2 C146.2 C147.2 C148.2 C149.2 C150.2 C151.2 C152.2 C153.2 C154.2 C155.2 C156.2 C157.2 C158.2 C159.2 C160.2 C161.2 C162.2 C163.2 C164.2 C165.2 C166.2 C167.2 C168.2 C169.2 C170.2 C171.2 C172.2 C173.2 C174.2 C175.2 C176.2 C177.2 C178.2 C179.2 C180.2 C181.2 C182.2 C183.2 C184.2 C185.2 C186.2 C187.2 C188.2 C189.2 C190.2 C191.2 C192.2 C193.2 C194.2 C195.2 C196.2 C197.2 C198.2 C199.2 C200.2 C201.2 C202.2 C203.2 C204.2 C205.2 C210.2 C211.2 C212.2 D14.2 J10.10 J11.6 J11.9 J11.14 J11.20 J11.25 J11.30 J11.34 J11.39 J12.10 J23.2 J23.10 JP22.2 JP25.2 Q3.E R283.2 R289.2 R319.2 R577.2 R584.2 SW11.9(B8) SW11.10(B7) SW11.11(B6) SW11.12(B5) SW11.13(B4) SW11.14(B3) SW11.15(B2) SW11.16(B1) SW12.1 SW12.3 SW13.2 SW13.4 SW14.9(B8) SW14.10(B7) SW14.11(B6) SW14.12(B5) SW14.13(B4) SW14.14(B3) SW14.15(B2) SW14.16(B1) TP29.1 TP30.1 TP32.1 U2.A4(VSSSDQ) U2.A7(VSSSDQ) U2.A10(VSSSDQ) U2.A13(VSSSDQ) U2.A16(VSSSDQ) U2.A19(VSSSDQ) U2.A20(VSSSDQ) U2.A23(VSSSDQ) U2.AB21(VSS) U2.AC5(VSS) U2.AC8(VSS) U2.AC10(VSS) U2.AC14(VSS) U2.AC17(VSS) U2.AD2(VSSADC) U2.AD24(VSS) U2.AE20(VSS) U2.B2(VSSSDQ) U2.B3(VSSSDQ) U2.B5(VSSSDQ) U2.B6(VSSSDQ) U2.B8(VSSSDQ) U2.B9(VSSSDQ) U2.B10(SD7_RXDP) U2.B11(VSSSDQ) U2.B12(VSSSDQ) U2.B13(SD6_RXDP) U2.B14(VSSSDQ) U2.B15(VSSSDQ) U2.B16(SD5_RXDN) U2.B17(VSSSDQ) U2.B18(VSSSDQ) U2.B19(SD4_RXDN) U2.B20(SD4_RXDP) U2.B21(VSSSDQ) U2.B22(VSSSDQ) U2.B23(SD2_RXDN) U2.B24(VSSSDQ) U2.B25(VSSSDQ) U2.C2(VSSSDQ) U2.C3(VSSSDQ) U2.C5(VSSSDQ) U2.C7(VSSSDQ) U2.C9(VSSSDQ) U2.C10(SD7_RXDN) U2.C11(VSSSDQ) U2.C12(SD6_RXDN) U2.C13(VSSSDQ) U2.C14(SDQ1_REFCLKP) U2.C15(VSSSDQ) U2.C16(SD5_RXDP) U2.C17(VSSSDQ) U2.C18(SD3_REXT) U2.C19(VSSSDQ) U2.C20(VSSSDQ) U2.C21(SD3_RXDP) U2.C22(SD3_RXDN) U2.C23(VSSSDQ) U2.C24(SD2_RXDP) U2.C25(VSSSDQ) U2.D1(VSSSDQ) U2.D4(VSSSDQ) U2.D6(VSSSDQ) U2.D7(VSSSDQ) U2.D8(VSSSDQ) U2.D9(SD_EXT1_REFCLKN) U2.D10(VSSSDQ) U2.D11(SD_EXT0_REFCLKP) U2.D12(VSSSDQ) U2.D13(SDQ1_REFCLKN) U2.D14(VSSSDQ) U2.D15(SD6_REXT) U2.D16(VSSSDQ) U2.D17(SD4_REXT) U2.D19(SD2_REXT) U2.D20(VSSSDQ) U2.D21(VSSSDQ) U2.D22(VSSSDQ) U2.D23(VSSSDQ) U2.D24(VSSSDQ) U2.D25(SD1_RXDN) U2.D26(VSSSDQ) U2.E2(VSSSDQ) U2.E3(VSSSDQ) U2.E5(VSSSDQ) U2.E10(SD_EXT1_REFCLKP) U2.E11(SD_EXT0_REFCLKN) U2.E13(SD7_REXT) U2.E14(VSSSDQ) U2.E20(SDQ0_REFCLKN) U2.E21(SD0_REXT) U2.E23(VSSSDQ) U2.E24(SD1_RXDP) U2.E25(VSSSDQ) U2.F2(VSSSDQ) U2.F4(VSSSDQ) U2.F5(VSSSDQ) U2.F6(VSSSDQ) U2.F7(VSSSDQ) U2.F8(VSSSDQ) U2.F10(VSSSDQ) U2.F13(VSSSDQ) U2.F14(VSSSDQ) U2.F18(VSSSDQ) U2.F20(SDQ0_REFCLKP) U2.F21(VSSSDQ) U2.F23(VSSSDQ) U2.F24(VSSSDQ) U2.F25(VSSSDQ) U2.G1(VSSSDQ) U2.G3(VSSSDQ) U2.G10(VSSSDQ) U2.G12(VSSSDQ) U2.G14(VSSSDQ) U2.G16(VSSSDQ) U2.G20(SD1_REXT) U2.G23(VSSSDQ) U2.G24(SD0_RXDP) U2.G25(SD0_RXDN) U2.G26(VSSSDQ) U2.H14(VSSSDQ) U2.H18(VSSSDQ) U2.H24(VSSSDQ) U2.H25(VSSSDQ) U2.J4(VSS) U2.J11(VSSSDQ) U2.J12(VSSSDQ) U2.J17(VSSSDQ) U2.K13(VSSSDQ) U2.K15(SD5_REXT) U2.K23(VSS) U2.L4(VSS) U2.L11(VSS) U2.L13(VSS) U2.L16(VSSSDQ) U2.M11(VSS) U2.M13(VSS) U2.M15(VSS) U2.M17(VSS) U2.M21(VSS) U2.N10(VSS) U2.N12(VSS) U2.N14(VSS) U2.N16(VSS) U2.P4(VSS) U2.P11(VSS) U2.P13(VSS) U2.P15(VSS) U2.P17(VSS) U2.R10(VSS) U2.R12(VSS) U2.R14(VSS) U2.R16(VSS) U2.R24(VSS) U2.T11(VSS) U2.T13(VSS) U2.T15(VSS) U2.T17(VSS) U2.U5(VSS) U2.U9(VSS) U2.U12(VSS) U2.U14(VSS) U2.U16(VSS) U2.U21(VSS) U2.V11(VSS) U2.V13(VSS) U2.Y3(VSS) U2.Y24(VSS) ; also on sheet 3 4 5 6 7 8 9 10 11 12 19 20 21 22 23 24 25 26 27 28
VBUS_5V_S: JP24.2 ; also on sheet 3
VCC_1V0: L4.2 ; also on sheet 9 27 28
VCC_1V8: J12.1 L3.1 L5.1 R284.1 R285.1 R286.1 R287.1 R288.1 R294.1 R297.1 R300.1 R309.1 R310.1 R311.1 R312.1 R313.1 R314.1 R315.1 R316.1 R317.1 R318.1 R320.1 R321.1 R322.1 R323.1 R324.1 R325.1 R326.1 R327.1 TP37.2 TP40.2 TP43.2 ; also on sheet 6 8 9 11 20 26 27 28
VCC_3V3: J10.1 JP23.1 R259.1 R260.1 R261.1 R262.1 R263.1 R264.1 R265.1 R266.1 R281.1 R293.1 R295.1 R296.1 R298.1 R299.1 R301.2 R302.2 R304.2 R305.1 R306.1 R308.2 R574.1 R575.1 R576.1 R578.1 R579.1 R580.1 R581.1 R582.1 R583.1 TP36.2 TP38.2 TP39.2 TP41.2 TP42.2 ; also on sheet 3 4 5 6 7 9 10 11 12 19 20 21 22 23 24 25 26 28
VCC_AUXA_NX: C154.1 C155.1 C156.1 C157.1 R291.2 TP34.2 U2.L12(VCCAUXA) U2.L14(VCCAUXA)
VCCAUX_1V8_NX: C192.1 C193.1 C194.1 C195.1 C196.1 C197.1 C198.1 C199.1 C200.1 C201.1 C202.1 C203.1 C204.1 C205.1 R292.2 TP35.2 U2.L17(VCCAUX) U2.M10(VCCAUX) U2.R17(VCCAUX) U2.U10(VCCAUX) U2.U15(VCCAUXH4) U2.U17(VCCAUXH5) U2.V9(VCCAUXH3) U2.V10(VCCAUXH3) U2.V15(VCCAUXH4) U2.V17(VCCAUXH5)
VCCCORE_NX: C158.1 C159.1 C160.1 C161.1 C162.1 C163.1 C164.1 C165.1 C166.1 C167.1 C168.1 C169.1 C170.1 C171.1 C172.1 C173.1 C174.1 C175.1 C176.1 C177.1 C178.1 C179.1 C180.1 C181.1 C182.1 C183.1 C184.1 C185.1 C186.1 C187.1 C188.1 C189.1 C190.1 C191.1 R290.2 TP33.2 U2.L10(VCC) U2.L15(VCC) U2.M12(VCC) U2.M14(VCC) U2.N11(VCC) U2.N13(VCC) U2.N15(VCC) U2.N17(VCC) U2.P10(VCC) U2.P12(VCC) U2.P14(VCC) U2.P16(VCC) U2.R11(VCC) U2.R13(VCC) U2.R15(VCC) U2.T9(VCCECLK) U2.T10(VCC) U2.T12(VCC) U2.T14(VCC) U2.T16(VCC) U2.U11(VCC) U2.U13(VCC) U2.V12(VCCECLK) U2.V14(VCCECLK) U2.V16(VCCECLK)
VCCIO0_3V3_NX: R293.2 TP36.1 ; also on sheet 12
VCCIO1_3V3_NX: R296.2 TP39.1 ; also on sheet 11
VCCIO2_3V3_NX: C134.1 C135.1 C136.1 C137.1 R299.2 TP42.1 U2.AA3(VCCIO2) U2.U4(VCCIO2)
VCCIO3_1V8_NX: C148.1 C149.1 C150.1 C151.1 C152.1 C153.1 R294.2 TP37.1 U2.AB5(VCCIO3) U2.AB8(VCCIO3) U2.AB10(VCCIO3) U2.AC3(VCCADC18)
VCCIO4_1V8_NX: C143.1 C144.1 C145.1 C146.1 C147.1 R297.2 TP40.1 U2.AB14(VCCIO4) U2.AB17(VCCIO4) U2.AD19(VCCIO4)
VCCIO5_1V8_NX: R300.2 TP43.1 ; also on sheet 11
VCCIO6_3V3_NX: C138.1 C139.1 C140.1 C141.1 R295.2 TP38.1 U2.R23(VCCIO6) U2.U20(VCCIO6)
VCCIO7_3V3_NX: C129.1 C130.1 C131.1 C132.1 R298.2 TP41.1 U2.K22(VCCIO7) U2.M20(VCCIO7)
AWK3_X3_CS: J23.9 R574.2 U3.F10(PT22A)
AWK3_X3_MCLK: R573.2 R576.2 R577.1 U3.A10(PT23B_PCLKC0_1)
AWK3_X3_SI: J23.8 R575.2 U3.G9(PT21D)
AWK3_X3_SO: J23.5 U3.E10(PT22B)
CPNX_QSPI2_CSN0: R423.2 ; also on sheet 23
CPNX_QSPI2_CSN1: R424.2 ; also on sheet 23
CPNX_QSPI2_DQ0_MOSI: R416.2 ; also on sheet 23
CPNX_QSPI2_DQ1_MISO: R417.2 ; also on sheet 23
CPNX_QSPI2_DQ2: R413.2 ; also on sheet 23
CPNX_QSPI2_DQ3: R415.2 ; also on sheet 23
CPNX_QSPI2_SCLK: R280.2 ; also on sheet 23
NX_12MHz: U2.N23(PL31A/PCLKT7_0) ; also on sheet 10
NX_BMC_LED_1: U2.L24(PL22B) ; also on sheet 25
NX_BMC_LED_2: U2.L23(PL24A) ; also on sheet 25
NX_BMC_LED_3: U2.L22(PL24B) ; also on sheet 25
NX_BMC_LED_4: U2.L20(PL26A) ; also on sheet 25
NX_BMC_LED_5: U2.L19(PL26B) ; also on sheet 25
NX_BMC_LED_6: U2.M26(PL28A/PCLKT7_2) ; also on sheet 25
NX_BMC_LED_7: U2.N26(PL28B) ; also on sheet 25
NX_BMC_LED_8: U2.N25(PL29A/PCLKT7_1) ; also on sheet 25
NX_BMC_LED_9: U2.N24(PL29B) ; also on sheet 25
NX_BMC_LED_10: U2.N22(PL31B) ; also on sheet 25
NX_PCH_BUTTON: C142.1 R282.2 TP31.1 U2.AB2(PR67B)
NX_PCH_DIP_SW1: R259.2 SW11.1(A1) U2.P26(PL40A)
NX_PCH_DIP_SW2: R260.2 SW11.2(A2) U2.P25(PL40B)
NX_PCH_DIP_SW3: R261.2 SW11.3(A3) U2.P24(PL42A/PCLKT6_0)
NX_PCH_DIP_SW4: R262.2 SW11.4(A4) U2.P23(PL42B)
NX_PCH_DIP_SW5: R263.2 SW11.5(A5) U2.P22(PL44A/PCLKT6_1)
NX_PCH_DIP_SW6: R264.2 SW11.6(A6) U2.P21(PL44B)
NX_PCH_DIP_SW7: R265.2 SW11.7(A7) U2.R21(PL46B)
NX_PCH_DIP_SW8: R266.2 SW11.8(A8) U2.R19(PL47A)
NX_PCH_LED_1: U2.V4(PR51B) ; also on sheet 25
NX_PCH_LED_2: U2.V5(PR53A) ; also on sheet 25
NX_PCH_LED_3: U2.V6(PR53B) ; also on sheet 25
NX_PCH_LED_4: U2.W7(PR55A) ; also on sheet 25
NX_PCH_LED_5: U2.W6(PR55B) ; also on sheet 25
NX_PCH_LED_6: U2.W5(PR56A) ; also on sheet 25
NX_PCH_LED_7: U2.W2(PR58B) ; also on sheet 25
NX_PCH_LED_8: U2.W1(PR60A) ; also on sheet 25
NX_PCH_LED_9: U2.Y1(PR60B) ; also on sheet 25
NX_PCH_LED_10: U2.Y4(PR62A) ; also on sheet 25
NX_PCH_UART_RXD: U2.W3(PR58A) ; also on sheet 10
NX_PCH_UART_TXD: U2.W4(PR56B) ; also on sheet 10
NX_X5_I3C_SCL_0: J10.2 JP58.1 ; also on sheet 7
NX_X5_I3C_SCL_1: J10.4 U2.L21(PL17B) ; also on sheet 7
NX_X5_I3C_SCL_2: J10.6 U2.K25(PL19B) ; also on sheet 7
NX_X5_I3C_SCL_3: J10.8 U2.L26(PL20B) ; also on sheet 6
NX_X5_I3C_SDA_0: J10.3 JP59.1 ; also on sheet 7
NX_X5_I3C_SDA_1: J10.5 U2.K24(PL19A) ; also on sheet 7
NX_X5_I3C_SDA_2: J10.7 U2.K26(PL20A) ; also on sheet 7
NX_X5_I3C_SDA_3: J10.9 U2.L25(PL22A) ; also on sheet 6
QSPI_PCH_QS_SEL: U2.T21(PL56A) ; also on sheet 23
X3_DIP_SW1: R327.2 SW14.1(A1) U3.E22(PR4A)
X3_DIP_SW2: R326.2 SW14.2(A2) U3.F22(PR5A)
X3_DIP_SW3: R325.2 SW14.3(A3) U3.G22(PR5B)
X3_DIP_SW4: R324.2 SW14.4(A4) U3.E21(PR4B)
X3_DIP_SW5: R323.2 SW14.5(A5) U3.G21(PR6A)
X3_DIP_SW6: R322.2 SW14.6(A6) U3.E20(PR4D)
X3_DIP_SW7: R321.2 SW14.7(A7) U3.G20(PR6B)
X3_DIP_SW8: R320.2 SW14.8(A8) U3.E19(PR4C)
X3_DONE: R302.1 R303.2 TP44.1 U3.E17(PT44D_DONE)
X3_INITN: D13.K(CATHODE) R304.1 TP45.1 U3.F16(PT44C_INITN)
X3_JTAGENB: JP25.1 R308.1 U3.E14(PT31C_JTAGENB)
X3_PROGRAMN: C210.1 JP22.1 R307.2 U3.E15(PT31D_PROGRAMN)
X3_RASP_IO0_ID_SD: J11.27 U3.B1(PT9A_L_GPLLT)
X3_RASP_IO1_ID_SC: J11.28 U3.A2(PT9B_L_GPLLC)
X3_RASP_IO2_SDA: J11.3 R578.2 U3.E6(PT9C)
X3_RASP_IO3_SCL: J11.5 R579.2 U3.F7(PT9D)
X3_RASP_IO4_GPCLK0: J11.7 U3.B2(PT10A)
X3_RASP_IO5: J11.29 U3.A3(PT10B)
X3_RASP_IO6: J11.31 U3.C3(PT10C)
X3_RASP_IO7_CE1: J11.26 R582.2 U3.C4(PT10D)
X3_RASP_IO8_CE0: J11.24 R581.2 U3.B3(PT11A)
X3_RASP_IO9_MISO: J11.21 U3.A4(PT11B)
X3_RASP_IO10_MOSI: J11.19 R580.2 U3.F8(PT11C)
X3_RASP_IO11_SCLK: J11.23 R583.2 R584.1 U3.B10(PT23A_PCLKT0_1)
X3_RASP_IO12_PWM0: J11.32 U3.G8(PT11D)
X3_RASP_IO13_PWM1: J11.33 U3.B4(PT12A)
X3_RASP_IO14_TXD: J11.8 U3.A5(PT12B)
X3_RASP_IO15_RXD: J11.10 U3.D5(PT12C)
X3_RASP_IO16: J11.36 U3.C5(PT12D)
X3_RASP_IO17: J11.11 U3.B5(PT13A)
X3_RASP_IO18_PCM_CLK: J11.12 U3.A6(PT13B)
X3_RASP_IO19_PCM_FS: J11.35 U3.D6(PT13C)
X3_RASP_IO20_PCM_DIN: J11.38 U3.E7(PT13D)
X3_RASP_IO21_PCM_DOUT: J11.40 U3.B6(PT14A)
X3_RASP_IO22: J11.15 U3.A7(PT14B)
X3_RASP_IO23: J11.16 U3.C6(PT14C)
X3_RASP_IO24: J11.18 U3.D7(PT14D)
X3_RASP_IO25: J11.22 U3.C8(PT15A)
X3_RASP_IO26: J11.37 U3.D8(PT15B)
X3_RASP_IO27: J11.13 U3.B8(PT20A)
X03_SCM_TXCLK_N: U3.A11(PT24B) ; also on sheet 26
X03_SCM_TXCLK_P: U3.B11(PT24A) ; also on sheet 26
X03_SCM_TXD_N: U3.E12(PT27B) ; also on sheet 26
X03_SCM_TXD_P: U3.D12(PT27A) ; also on sheet 26
X3_TCK: U3.D10(PT22C_TCK) ; also on sheet 24
X3_TDI: U3.E9(PT15D_TDI) ; also on sheet 24
X3_TDO: U3.E8(PT15C_TDO) ; also on sheet 24
X3_TMS: U3.C10(PT22D_TMS) ; also on sheet 24
X3_X5_I2C_FLT1_SCL_I: J23.1 U3.A9(PT21B) ; also on sheet 7
X3_X5_I2C_FLT1_SDA_I: J23.3 U3.B9(PT21A) ; also on sheet 7
X5_NX_ESPI_ALERT: R288.2 U2.AE11(PB116B/ADC_CN8) ; also on sheet 8
X5_NX_ESPI_CLK: R289.1 U2.AC12(PB112A/PCLKT3_0/ADC_CP4) ; also on sheet 8
X5_NX_ESPI_CS: R284.2 U2.AD12(PB112B/PCLKC3_0/ADC_CN4) ; also on sheet 8
X5_NX_ESPI_DATA0: R287.2 U2.AA12(PB110A/VREF3_1/ADC_CP10) ; also on sheet 8
X5_NX_ESPI_DATA1: R286.2 U2.AB12(PB110B/ADC_CN10) ; also on sheet 8
X5_NX_ESPI_RSTN: R285.2 U2.AD11(PB116A/ADC_CP8) ; also on sheet 8
X5_NX_LTPI_N_0: U2.AE10(PB128B) ; also on sheet 8
X5_NX_LTPI_N_1: U2.AF9(PB126B) ; also on sheet 8
X5_NX_LTPI_N_2: R599.2 U2.AC11(PB118B/PCLKC3_1/COMP2IN) ; also on sheet 8
X5_NX_LTPI_N_3: R600.2 U2.AA11(PB120B/ADC_CN13) ; also on sheet 8
X5_NX_LTPI_P_0: U2.AD10(PB128A) ; also on sheet 8
X5_NX_LTPI_P_1: U2.AF10(PB126A) ; also on sheet 8
X5_NX_LTPI_P_2: R599.1 U2.AB11(PB118A/PCLKT3_1/COMP2IP) ; also on sheet 8
X5_NX_LTPI_P_3: R600.1 U2.Y11(PB120A/ADC_CP13) ; also on sheet 8
X5_NX_SGPIOA_0: U2.U2(PR44A/PCLKT2_1) ; also on sheet 6
X5_NX_SGPIOA_1: U2.T3(PR40A) ; also on sheet 6
X5_NX_SGPIOA_2: U2.T2(PR40B) ; also on sheet 6
X5_NX_SGPIOA_3: U2.U1(PR42B) ; also on sheet 6
X5_NX_SGPIOB_0: U2.U6(PR46A/PCLKT2_2) ; also on sheet 6
X5_NX_SGPIOB_1: U2.U7(PR46B) ; also on sheet 6
X5_NX_SGPIOB_2: U2.V8(PR47A) ; also on sheet 6
X5_NX_SGPIOB_3: U2.V7(PR47B) ; also on sheet 6
X5_X3_CFG_SCL: U3.B12(PT27C_SCL/PCLKT0_0) ; also on sheet 5
X5_X3_CFG_SDA: U3.A12(PT27D_SDA/PCLKC0_0) ; also on sheet 5
X5_X3_ESPI_ALERT0n: R315.2 U2.AF5(PB138B) U3.N20(PR19C) ; also on sheet 8
X5_X3_ESPI_ALERT1n: J12.9 R317.2 U2.AD6(PB140A) ; also on sheet 8
X5_X3_ESPI_CLK: J12.2 R319.1 U2.AB4(PB154A/PCLKT3_3/ADC_CP15) U3.M22(PR17A_PCLKT1_0) ; also on sheet 8
X5_X3_ESPI_CS0_1_n: J12.3 JP60.2
X5_X3_ESPI_CS0n: JP60.3 R309.2 U2.AC4(PB154B/PCLKC3_3/ADC_CN15) U3.M21(PR17B_PCLKC1_0) ; also on sheet 8
X5_X3_ESPI_CS1n: JP60.1 R310.2 U2.AA5(PB148B/PCLKC3_2/COMP3IN) ; also on sheet 8
X5_X3_ESPI_DQ0: J12.4 R311.2 U2.AD3(PB156A/LRC_GPLL0T_IN) U3.M20(PR17C) ; also on sheet 8
X5_X3_ESPI_DQ1: J12.5 R312.2 U2.AD4(PB152A/ADC_CP12) U3.M19(PR17D) ; also on sheet 8
X5_X3_ESPI_DQ2: J12.6 R313.2 U2.AE3(PB156B/LRC_GPLL0C_IN/VREF3_2) U3.N22(PR19A) ; also on sheet 8
X5_X3_ESPI_DQ3: J12.7 R314.2 U2.AE4(PB152B/ADC_CN12) U3.P21(PR19B) ; also on sheet 8
X5_X3_ESPI_RST0n: R316.2 U2.AD5(PB144A) U3.N19(PR19D) ; also on sheet 8
X5_X3_ESPI_RST1n: J12.8 R318.2 U2.AE5(PB144B) ; also on sheet 8
X5_X3_LTPI_RXCLK_N: C207.2 ; also on sheet 6
X5_X3_LTPI_RXCLK_N_DC: C207.1 U3.B19(PT41B)
X5_X3_LTPI_RXCLK_P: C206.2 ; also on sheet 6
X5_X3_LTPI_RXCLK_P_DC: C206.1 U3.A18(PT41A)
X5_X3_LTPI_RXD_N: C209.2 ; also on sheet 6
X5_X3_LTPI_RXD_N_DC: C209.1 U3.B18(PT40B)
X5_X3_LTPI_RXD_P: C208.2 ; also on sheet 6
X5_X3_LTPI_RXD_P_DC: C208.1 U3.A17(PT40A)
X_CC_SMBUS_ALERTN0: U2.T20(PL56B) ; also on sheet 7
X_CC_SMBUS_ALERTN1: U2.U18(PL60B) ; also on sheet 7
X_CC_SMBUS_ALERTN2: U2.U24(PL64A) ; also on sheet 7
X_CC_SMBUS_ALERTN3: U2.V19(PL65B) ; also on sheet 7
X_CC_SMBUS_SCL0: U2.R18(PL47B) ; also on sheet 7
X_CC_SMBUS_SCL1: U2.T18(PL58B) ; also on sheet 7
X_CC_SMBUS_SCL2: U2.U22(PL62A) ; also on sheet 7
X_CC_SMBUS_SCL3: U2.U25(PL64B) ; also on sheet 7
X_CC_SMBUS_SDA0: U2.T23(PL55B) ; also on sheet 7
X_CC_SMBUS_SDA1: U2.U19(PL60A) ; also on sheet 7
X_CC_SMBUS_SDA2: U2.U23(PL62B) ; also on sheet 7
X_CC_SMBUS_SDA3: U2.V18(PL65A) ; also on sheet 7
N16799494: R281.2 R282.1 SW12.2 SW12.4
N16805562: R417.1 U2.T22(PL49B)
N16805570: R416.1 U2.R25(PL51A)
N16805589: R423.1 U2.R26(PL51B)
N16805613: R415.1 U2.T26(PL53A)
N16805621: R413.1 U2.T25(PL53B)
N17094154: L3.2 R291.1 TP34.1
N17094213: L5.2 R292.1 TP35.1
N17722507: R424.1 U2.T24(PL55A)
N17737448: L4.1 R290.1 TP33.1
N17902190: R280.1 U2.R20(PL46A/PCLKT6_2)
N17958945: R283.1 U2.AC1(ADC_REFP0) U2.AC2(ADC_REFP1)
N18450803: D12.A(ANODE) R301.1
N18450821: D12.K(CATHODE) Q3.C
N18450851: Q3.B R303.1
N18452544: D13.A(ANODE) R305.2
N18454554: D14.1 R306.2 R307.1 SW13.1 SW13.3
N19815807: C211.1 J11.1 J11.17 JP23.2
N19815822: C212.1 J11.2 J11.4 JP24.1
N20134119: JP58.2 U2.K19(PL15B)
N20134126: JP59.2 U2.K21(PL17A)
N20189303: J23.7 R573.1

Not connected (* = marked no-connect by the designer): J23 4* 6*; U2 A2(NC)* A3(NC)* A5(NC)* A6(NC)* A8(SD7_TXDN)* A9(SD7_TXDP)* A11(SD6_TXDN)* A12(SD6_TXDP)* A14(SD5_TXDN)* A15(SD5_TXDP)* A17(SD4_TXDN)* A18(SD4_TXDP)* A21(SD3_TXDN)* A22(SD3_TXDP)* A24(SD2_TXDN)* A25(SD2_TXDP)* AA1(PR65A) AA2(PR64A) AA4(PR62B) AA6(PB146B/ADC_CN14) AA7(PB136A) AA8(NC)* AA9(NC)* AA10(PB124B) AA13(PB100A/PCLKT4_2/ADC_CP7) AA14(PB94B) AA15(NC)* AA16(NC)* AA17(PB82A) AA18(PB60B) AA19(NC)* AA20(NC)* AA25(NC)* AA26(NC)* AB1(PR65B) AB3(PR67A) AB6(PB142A) AB7(PB134B) AB9(PB132A) AB13(PB100B/PCLKC4_2/ADC_CN7) AB15(PB86A) AB16(NC)* AB18(PB58B/PCLKC4_1) AB19(PB58A/PCLKT4_1) AC6(PB142B) AC7(PB134A) AC9(PB132B) AC13(PB104A/ADC_CP9) AC15(PB86B) AC16(NC)* AC18(PB80A) AC19(PB56B) AD1(ADC_DN1)* AD7(NC)* AD8(NC)* AD9(PB130A) AD13(PB104B/ADC_CN9) AD14(PB96A) AD15(PB88A) AD16(NC)* AD17(NC)* AD18(PB80B) AD20(PB56A) AD21(PB52A/PCLKT4_0) AE1(ADC_DP1)* AE2(ADC_DN0)* AE6(PB140B) AE7(NC)* AE8(NC)* AE9(PB130B) AE12(PB106B/PCLKC4_3) AE13(PB106A/PCLKT4_3) AE14(PB96B) AE15(PB88B) AE16(NC)* AE17(NC)* AE18(NC)* AE19(PB64B) AE21(PB52B/PCLKC4_0) AE22(PB50A/VREF4_1) AE23(PB50B) AF2(ADC_DP0)* AF3(PB150B/ADC_CN11) AF4(PB150A/ADC_CP11) AF6(PB138A) AF7(NC)* AF8(NC)* AF11(PB114B/COMP1IN) AF12(PB114A/COMP1IP) AF13(PB102B/ADC_CN6) AF14(PB102A/ADC_CP6) AF15(PB90A) AF16(PB90B) AF17(NC)* AF18(NC)* AF19(PB64A) AF20(PB66B) AF21(PB66A) AF22(PB54A) AF23(PB54B) B1(NC)* B4(NC)* B7(NC)* B26(SD1_TXDN)* C1(NC)* C4(NC)* C6(NC)* C8(NC)* C26(SD1_TXDP)* D2(NC)* D3(NC)* D5(NC)* D18(SD3_REFRET)* E1(NC)* E4(NC)* E6(NC)* E7(NC)* E8(NC)* E9(NC)* E12(SD7_REFRET)* E15(SD6_REFRET)* E16(VCCPLLSD4)* E17(SD4_REFRET)* E18(VCCPLLSD3)* E19(SD2_REFRET)* E22(SD0_REFRET)* E26(SD0_TXDN)* F1(NC)* F3(NC)* F9(NC)* F11(NC)* F12(VCCPLLSD7)* F15(VCCPLLSD6)* F16(VCCSD4-2)* F17(VCCSD4-1)* F19(VCCPLLSD2)* F22(VCCPLLSD0)* F26(SD0_TXDP)* G8(NC)* G9(NC)* G11(NC)* G13(VCCSD7-1)* G15(VCCSD5-2)* G17(VCCSD3-1)* G18(VCCSD1-1)* G19(VCCSD0-1)* G21(SD1_REFRET)* G22(VCCPLLSD1)* H8(NC)* H9(NC)* H10(NC)* H11(NC)* H12(NC)* H13(VCCSD7-2)* H15(VCCPLLSD5)* H16(VCCSD5-1)* H17(VCCSD3-2)* H19(VCCSD0-2)* H20(PL3A/ULC_GPLL0T_IN) H21(PL3B/ULC_GPLL0C_IN) H22(PL4A) H23(PL4B) H26(PL6A) J8(NC)* J9(NC)* J10(NC)* J13(VCCAUXSDQ1)* J14(VCCSD6-1)* J15(SD5_REFRET)* J16(VCCAUXSDQ0)* J18(VCCSD1-2)* J19(PL13A) J20(PL11B) J21(PL11A) J22(PL10B) J23(PL10A) J24(PL8B) J25(PL8A) J26(PL6B) K9(NC)* K10(NC)* K11(NC)* K12(NC)* K14(VCCSD6-2)* K16(VCCSD2-2)* K17(VCCSD2-1)* K18(PL15A) K20(PL13B) L18(NC)* M16(VCCSDCK)* M18(NC)* M19(NC)* M22(NC)* M23(NC)* M24(NC)* M25(NC)* N18(NC)* N19(PL35A) N20(PL33B) N21(PL33A) P1(NC)* P2(NC)* P3(NC)* P6(NC)* P7(NC)* P18(PL35B) P19(PL38A) P20(PL38B) R1(NC)* R2(NC)* R3(NC)* R22(PL49A) T1(PR42A/PCLKT2_0) T19(PL58A) U3(PR44B) V1(PR49A) V2(PR49B) V3(PR51A) V20(PL67A) V21(PL67B) W8(NC)* W9(NC)* W10(PB122B) W11(PB122A) W12(PB108B/VREF4_2) W13(PB98A/ADC_CP5) W14(PB92B) W15(PB92A) W16(PB84B) W17(PB62A) W18(PB62B) W19(NC)* W20(NC)* Y2(PR64B) Y5(PB148A/PCLKT3_2/COMP3IP) Y6(PB146A/ADC_CP14) Y7(PB136B) Y8(NC)* Y9(NC)* Y10(PB124A) Y12(PB108A) Y13(PB98B/ADC_CN5) Y14(PB94A) Y15(NC)* Y16(PB84A) Y17(PB82B) Y18(PB60A) Y19(NC)* Y20(NC)* Y21(NC)* Y22(NC)* Y25(NC)* Y26(NC)*; U3 A8(PT20B) A13(PT29A) A14(PT30A) A15(PT38A) A16(PT39A) A19(PT42A) A20(PT43A_R_GPLLT) A21(PT44A_R_GPLLT) AA22(PR29A) B13(PT29B) B14(PT30B) B15(PT38B) B17(PT39B) B20(PT42B) B21(PT43B_R_GPLLC) B22(PT44B_R_GPLLC) C9(PT20C) C13(PT29C) C14(PT30C) C15(PT38C) C17(PT39C) C18(PT41C) C19(PT43C) C20(PT43D) C21(PR2A_R_GPLLT_FB) C22(PR2B_R_GPLLC_FB) D9(PT20D) D11(PT24D) D13(PT29D) D14(PT30D) D15(PT38D) D16(PT39D) D17(PT40D) D18(PT41D) D19(PR3C) D20(PR3D) D21(PR3B_R_GPLLC_IN) D22(PR3A_R_GPLLT_IN) E11(PT24C) E13(PT28C) E16(PT40C) F9(PT21C) F11(PT23D) F12(PT28B) F13(PT28D) F14(PT31B) F15(PT42C) F17(PR2C) F18(PR5C) F19(PR5D) G11(PT23C) G12(PT28A) G14(PT31A) G15(PT42D) G16(PR2D) G17(PR7C) G18(PR6D) G19(PR6C) H16(PR10D) H17(PR10C) H18(PR10B) H19(PR10A) H20(PR7D) H21(PR7B) H22(PR7A) J16(PR11A) J17(PR11B) J18(PR11C) J19(PR11D) J20(PR12C) J21(PR12A) J22(PR12B) K16(PR13D) K17(PR13C) K18(PR13B) K19(PR13A) K20(PR12D) K22(PR16A) L16(PR14B) L17(PR14A) L19(PR14C) L20(PR14D) L21(PR16B) L22(PR16C) M16(PR18A) M17(PR16D) N16(PR18B) N17(PR18C) N18(PR18D) P16(PR24B)* P17(PR24A) P18(PR21D) P19(PR21C) P20(PR20D) P22(PR20C) R16(PR26C) R17(PR26B) R18(PR26A) R19(PR25D) R20(PR25C) R21(PR20B) R22(PR20A) T17(PR27C) T18(PR27B) T19(PR27A) T20(PR26D) T21(PR21B) T22(PR21A) U17(PR29C) U18(PR28D) U19(PR28C) U20(PR27D) U21(PR24D) U22(PR24C) V18(PR30A) V19(PR29D) V22(PR25A) W19(PR30C) W20(PR30B) W21(PR28B) W22(PR25B) Y20(PR30D) Y21(PR29B) Y22(PR28A)

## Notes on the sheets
sheet 13
- LEDs Signal Map
- U2
  Pin
- Signal
- LED
- L24
- NX_BMC_LED_1
- D25
- L23
- NX_BMC_LED_2
- D26
- L22
- NX_BMC_LED_3
- D27
- L20
- NX_BMC_LED_4
- D28
- BANK 7
- L19
- NX_BMC_LED_5
- D29
- 3.3V
- M26
- NX_BMC_LED_6
- D30
- N26
- NX_BMC_LED_7
- D31
- N25
- NX_BMC_LED_8
- D32
- N24
- NX_BMC_LED_9
- D33
- N22
- NX_BMC_LED_10
- D34
- I3C HEADER
sheet 14
- WR GPIO BANK
- LEDs Signal Map
- U2
  Pin
- Switch Signal Map
- Signal
- LED
- V4
- NX_PCH_LED_1
- D37
- U2
  Pin
- V5
- NX_PCH_LED_2
- D48
- Signal
- SWITCH
- V6
- NX_PCH_LED_3
- D39
- P26
- NX_PCH_DIP_SW1
- 1
- W7
- NX_PCH_LED_4
- D50
- P25
- NX_PCH_DIP_SW2
- 2
- W6
- NX_PCH_LED_5
- D42
- P24
- NX_PCH_DIP_SW3
- 3
- W5
- NX_PCH_LED_6
- D52
- P23
- NX_PCH_DIP_SW4
- 4
- W2
- NX_PCH_LED_7
- D43
- P22
- NX_PCH_DIP_SW5
- 5
- W1
- NX_PCH_LED_8
- D53
- P21
- NX_PCH_DIP_SW6
- 6
- Y1
- NX_PCH_LED_9
- D44
- R21
- NX_PCH_DIP_SW7
- 7
- BANK 2
- Y4
- NX_PCH_LED_10
- D54
- R19
- NX_PCH_DIP_SW8
- 8
- 3.3V
- GP BUTTON
- DIP SWITCH
- BANK 6
  3.3V
sheet 15
- DNP
- BANK 3
- BANK 4
- 1.8V
- 1.8V
sheet 16
- FPGA POWER
sheet 17
- DONE LED
- 3.3V
- INITN LED
- PROGRAMN
- DNP
- DNP
- AARDVARK HEADER
- RASPBERRY PI HEADER
sheet 18
- 1.8V
- DIP Switch Signal Map
- U3
  Pin
- Signal
- SWITCH
- E22
- X3_DIP_SW1
- 1
- F22
- X3_DIP_SW2
- 2
- DIP SWITCH
- G22
- X3_DIP_SW3
- 3
- E21
- X3_DIP_SW4
- 4
- G21
- X3_DIP_SW5
- 5
- E20
- X3_DIP_SW6
- 6
- G20
- X3_DIP_SW7
- 7
- E19
- X3_DIP_SW8
- 8
